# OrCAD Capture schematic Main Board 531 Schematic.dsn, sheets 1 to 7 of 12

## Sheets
1 01 INDEX: size A3; title: COMET10 EVAL board - Index; rev: 531; company: ST Microelectronics
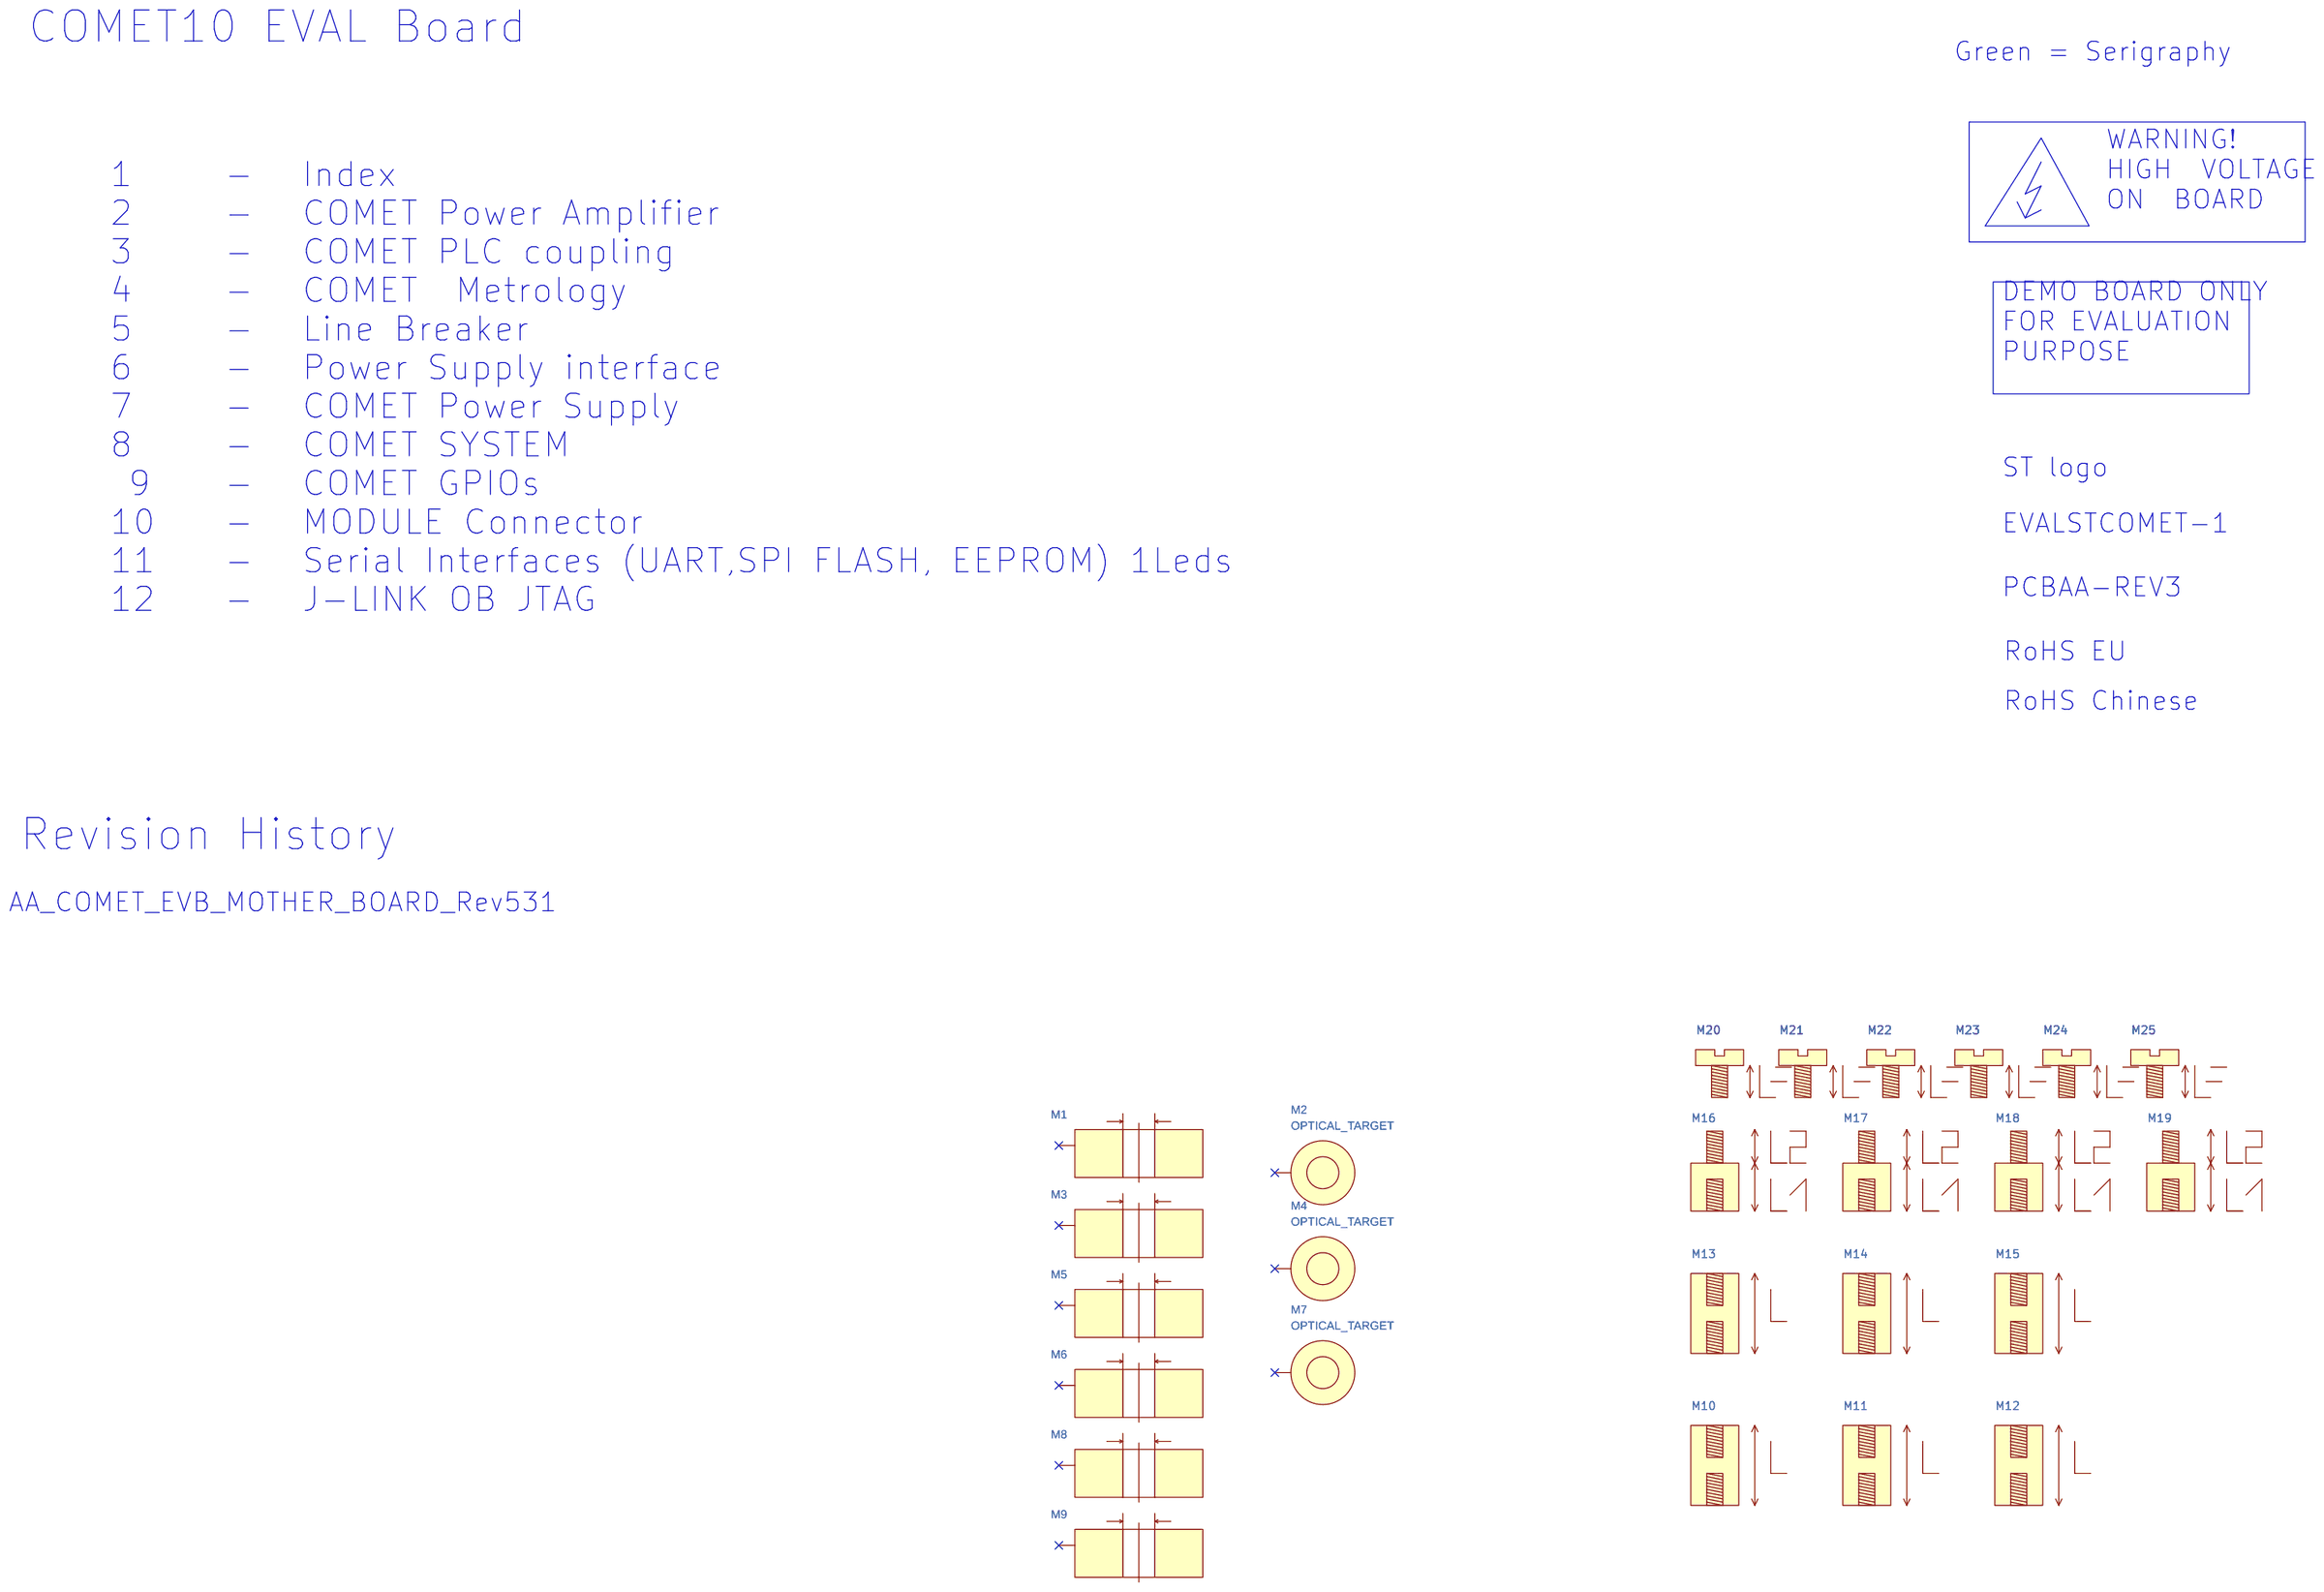
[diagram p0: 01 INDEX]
2 02 COMET POWER AMPLIFIER: size A3; title: COMET10 EVAL board - Differential power amplifier
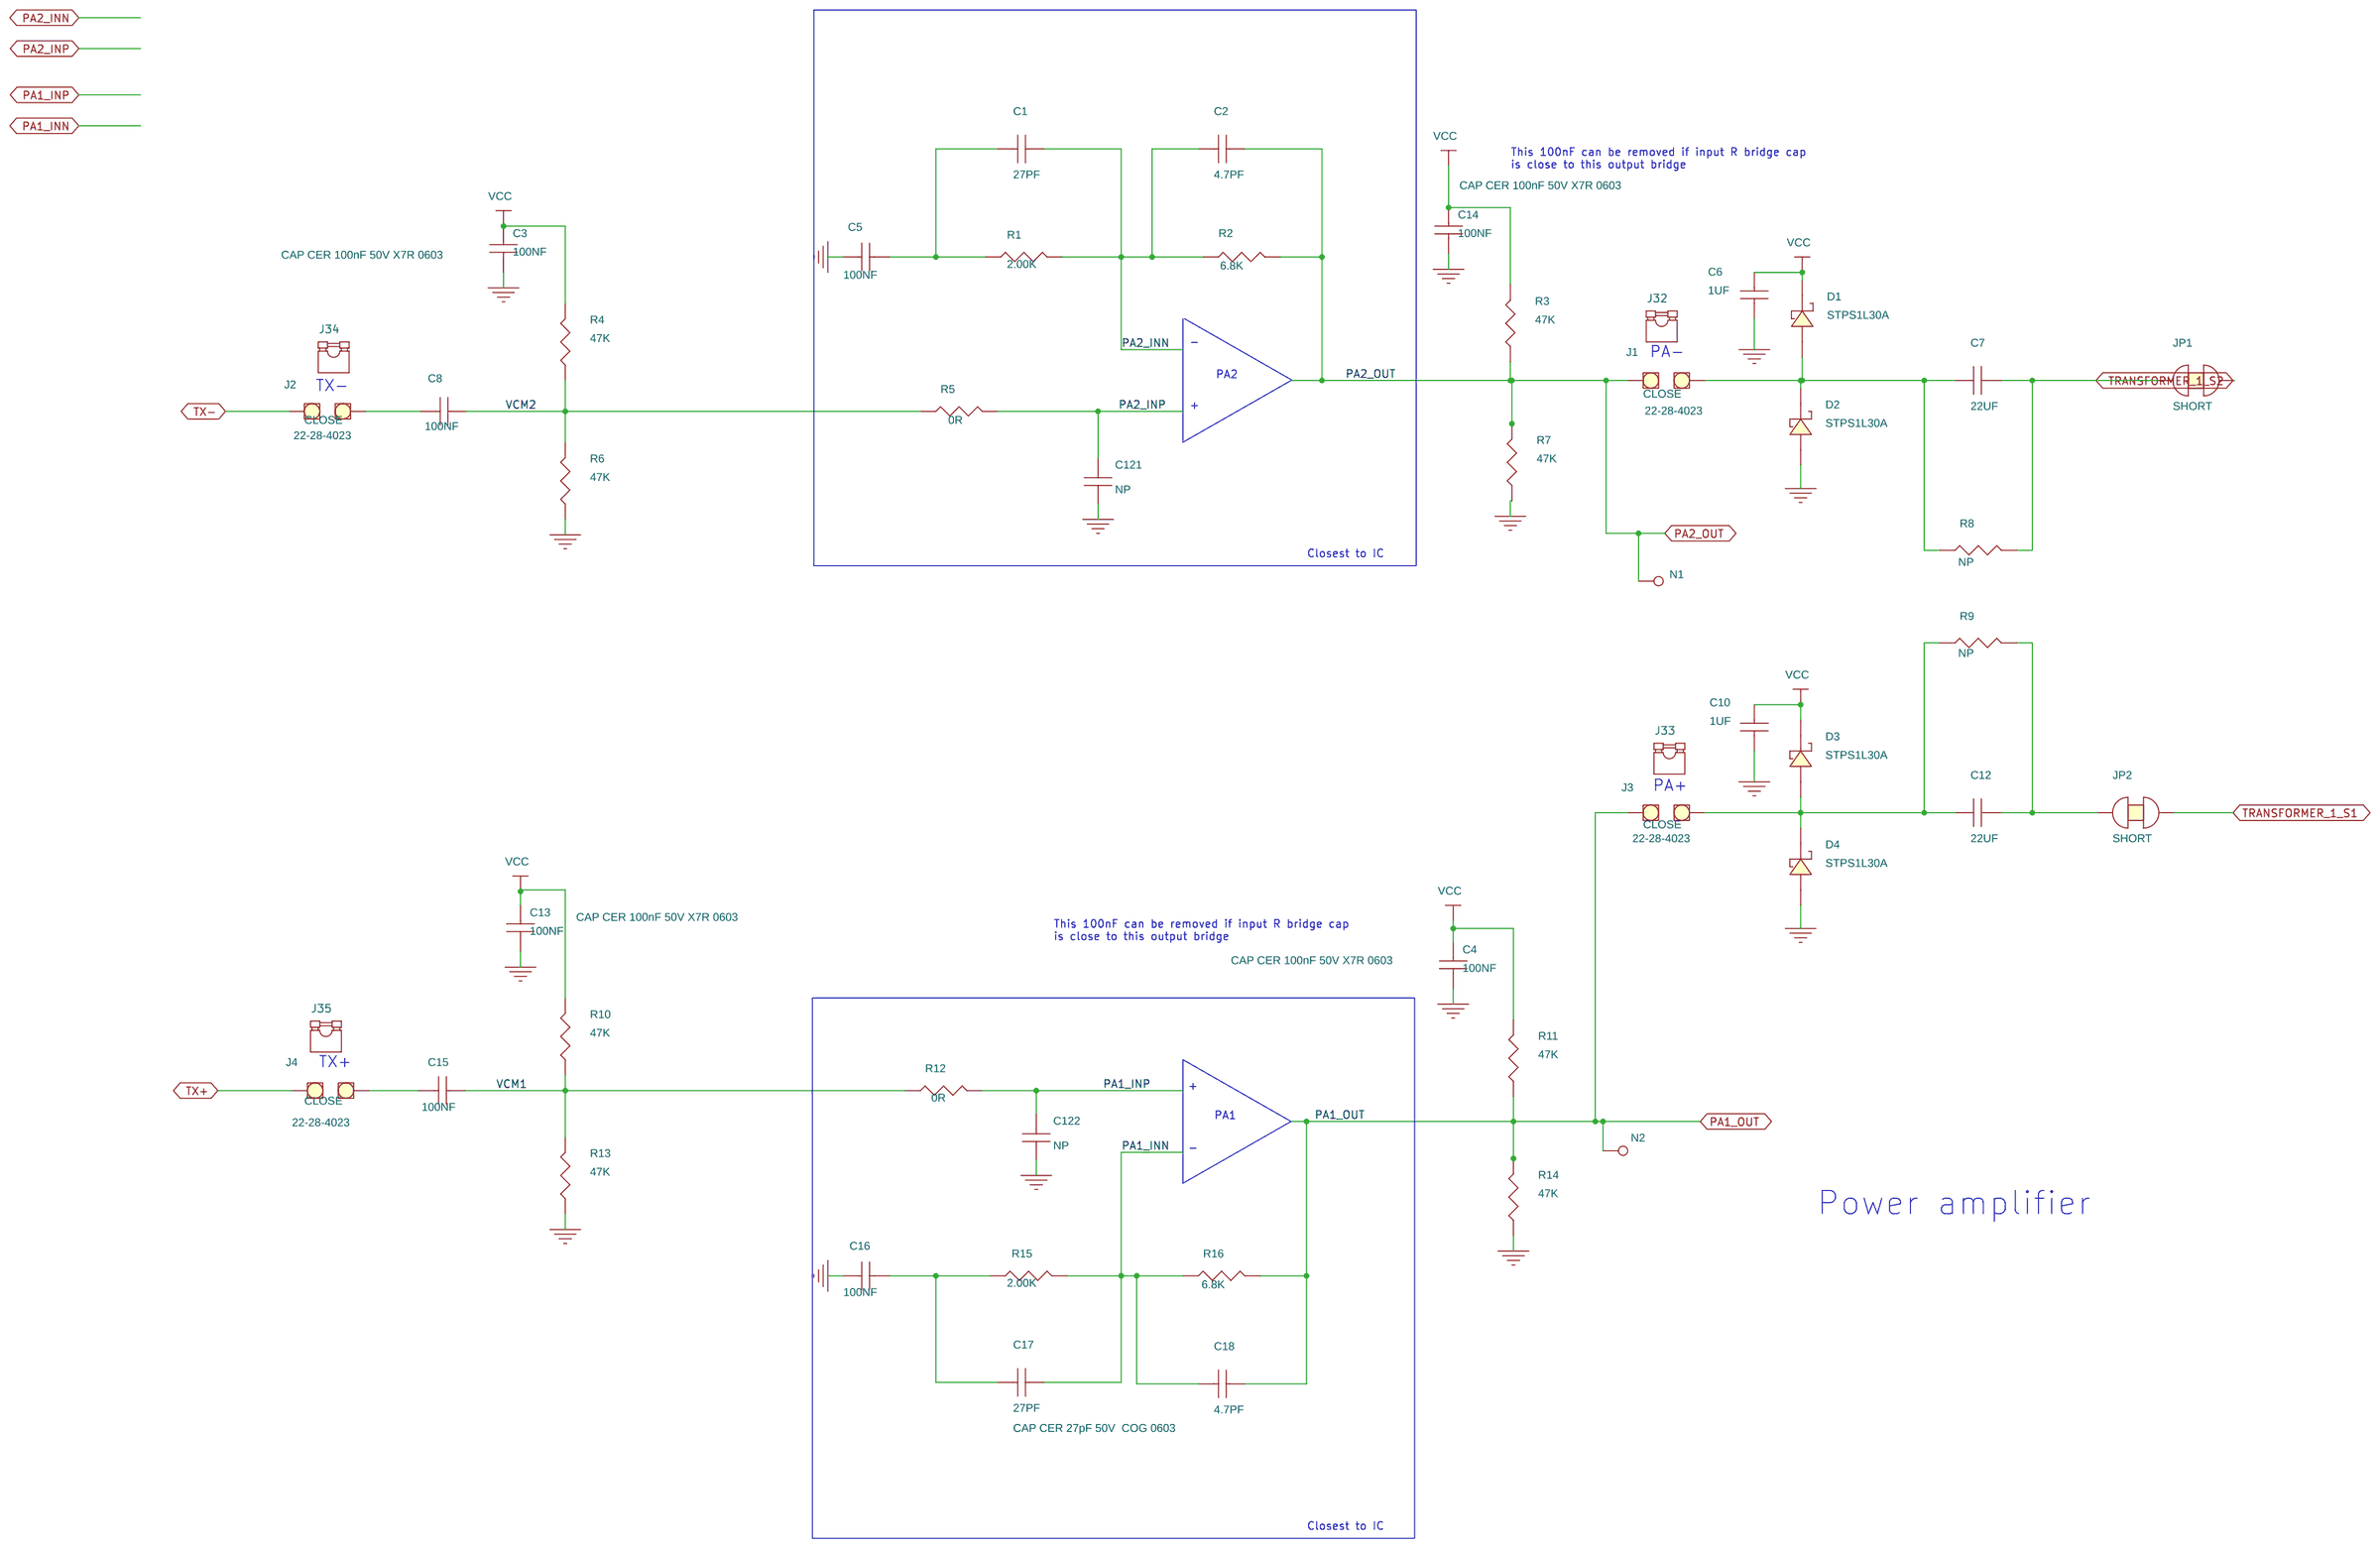
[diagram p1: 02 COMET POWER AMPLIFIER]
3 03 COMET PLC COUPLING: size A3; title: COMET10 EVAL board - PLC TX RX coupling, DAC, Zero Crossing
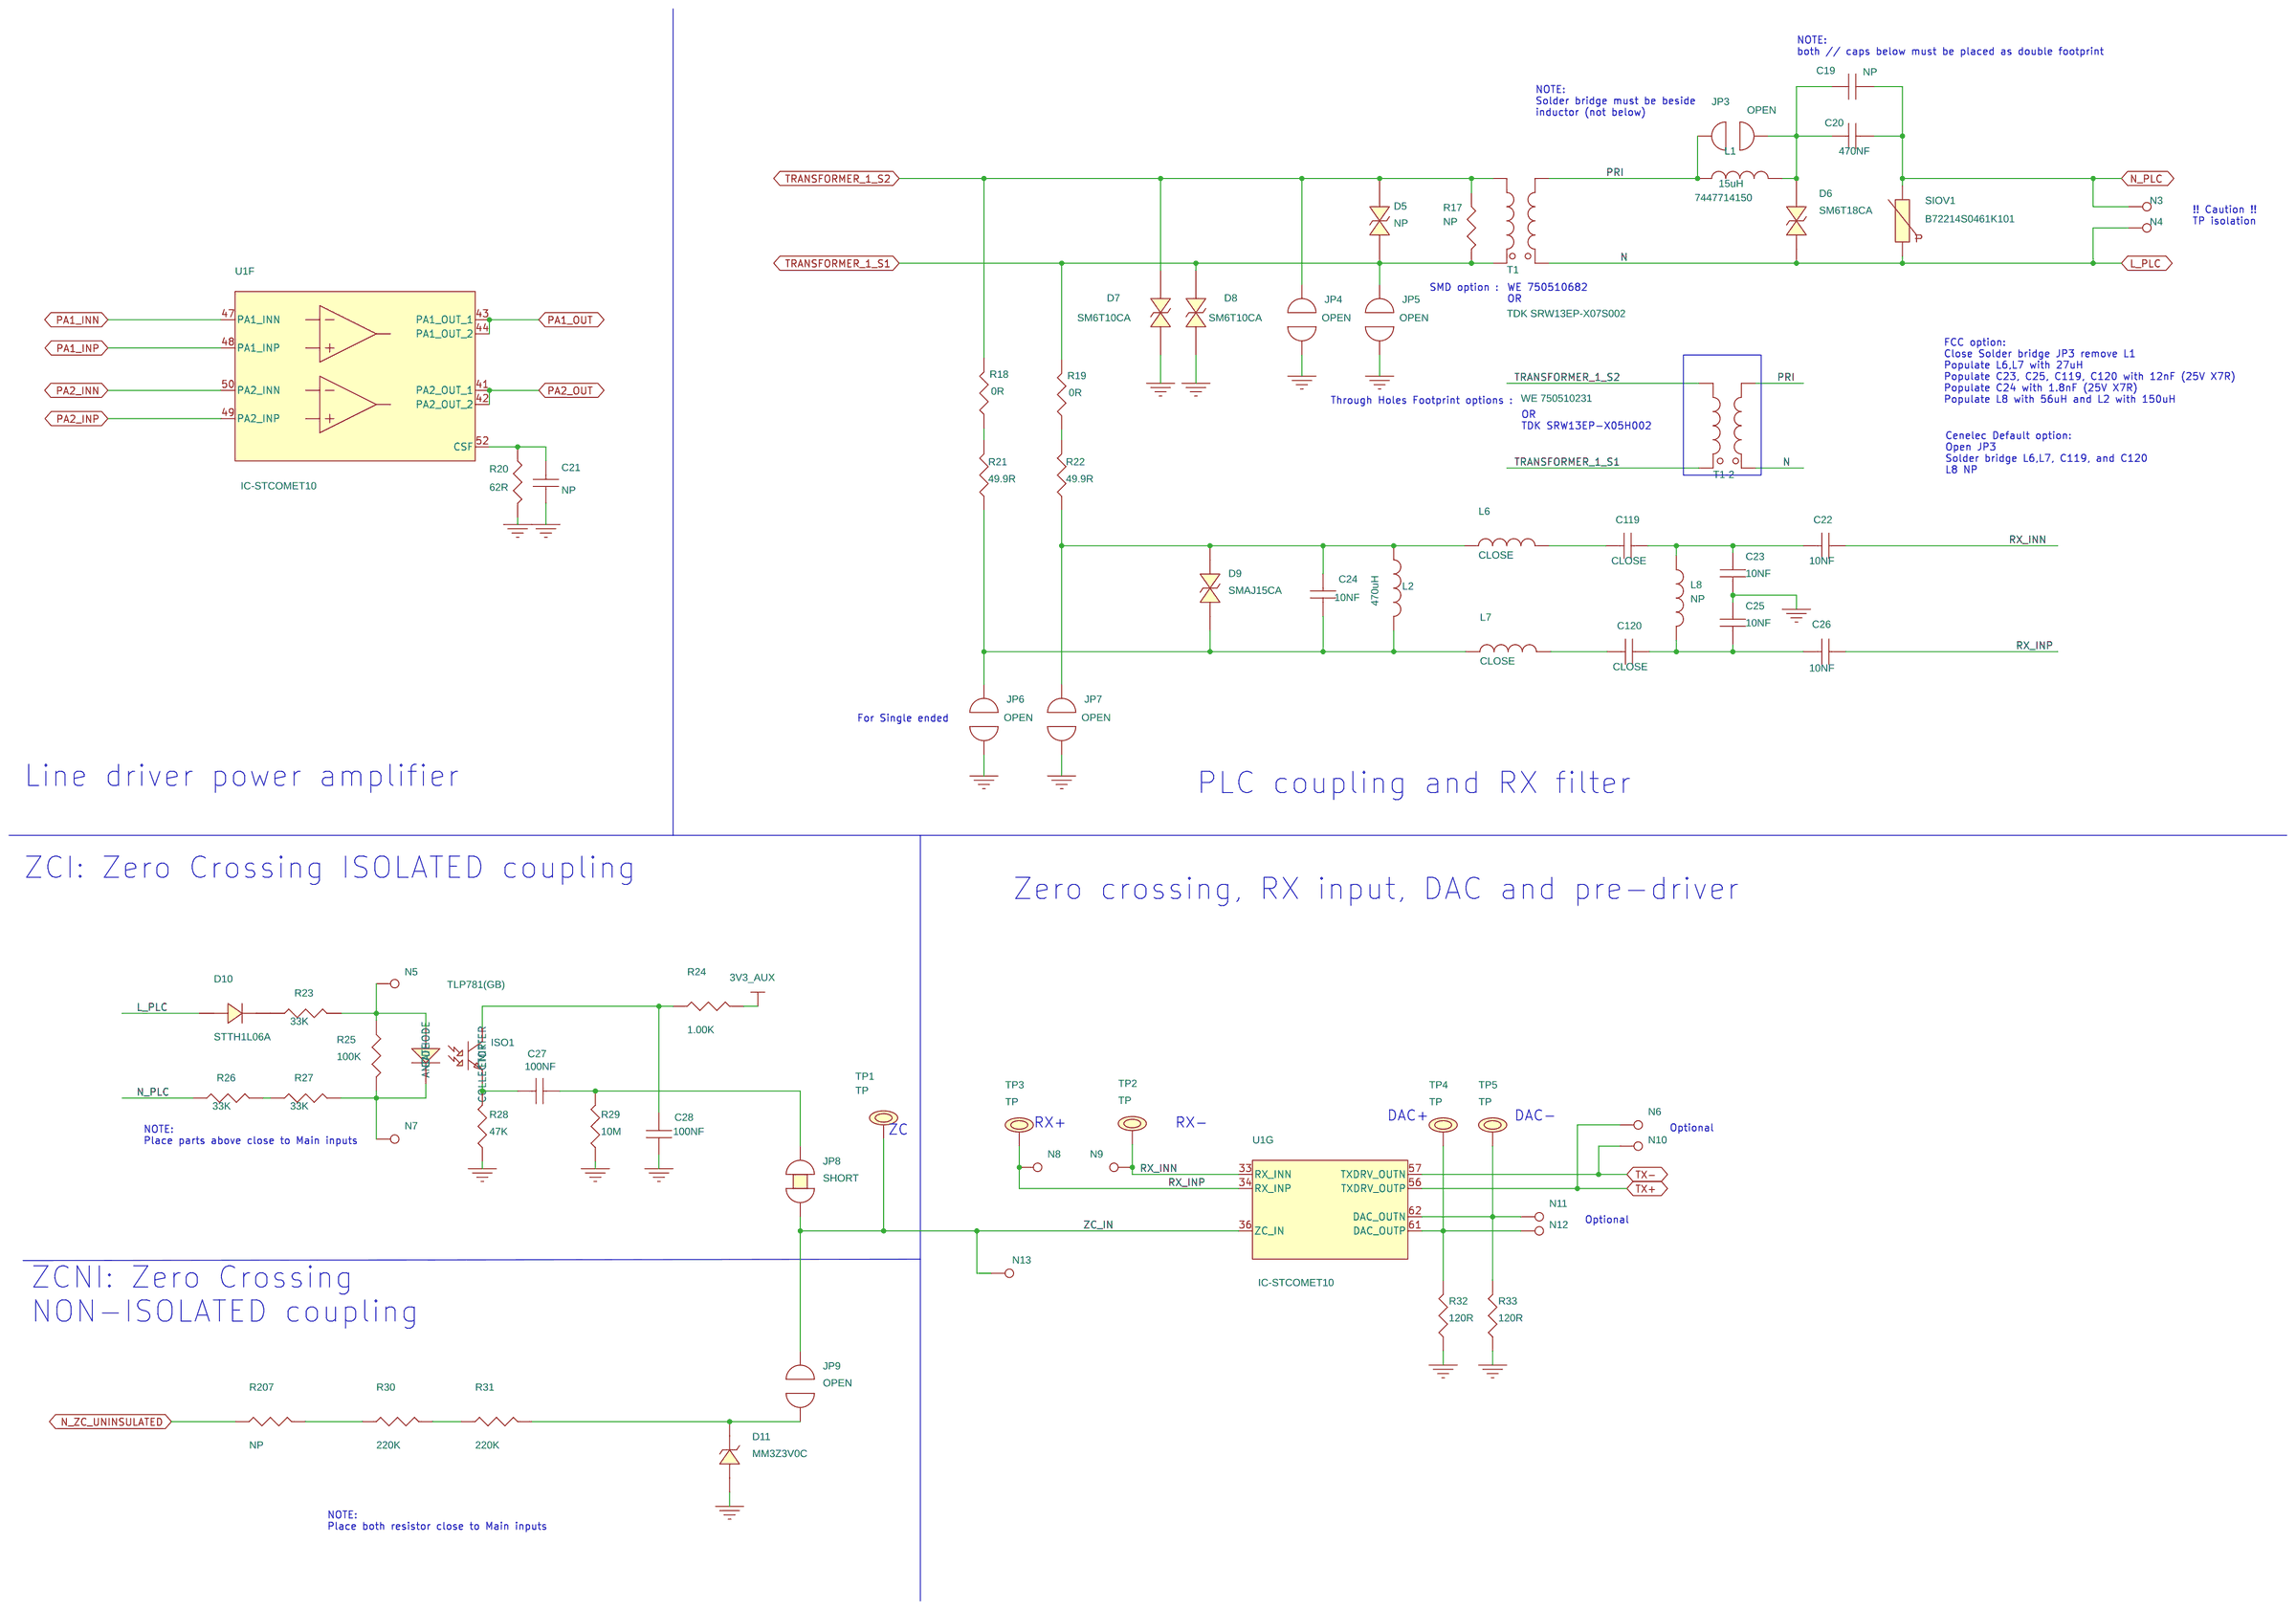
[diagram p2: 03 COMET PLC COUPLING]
4 04 COMET METROLOGY: size A3; title: COMET10 EVAL board - Metrology section
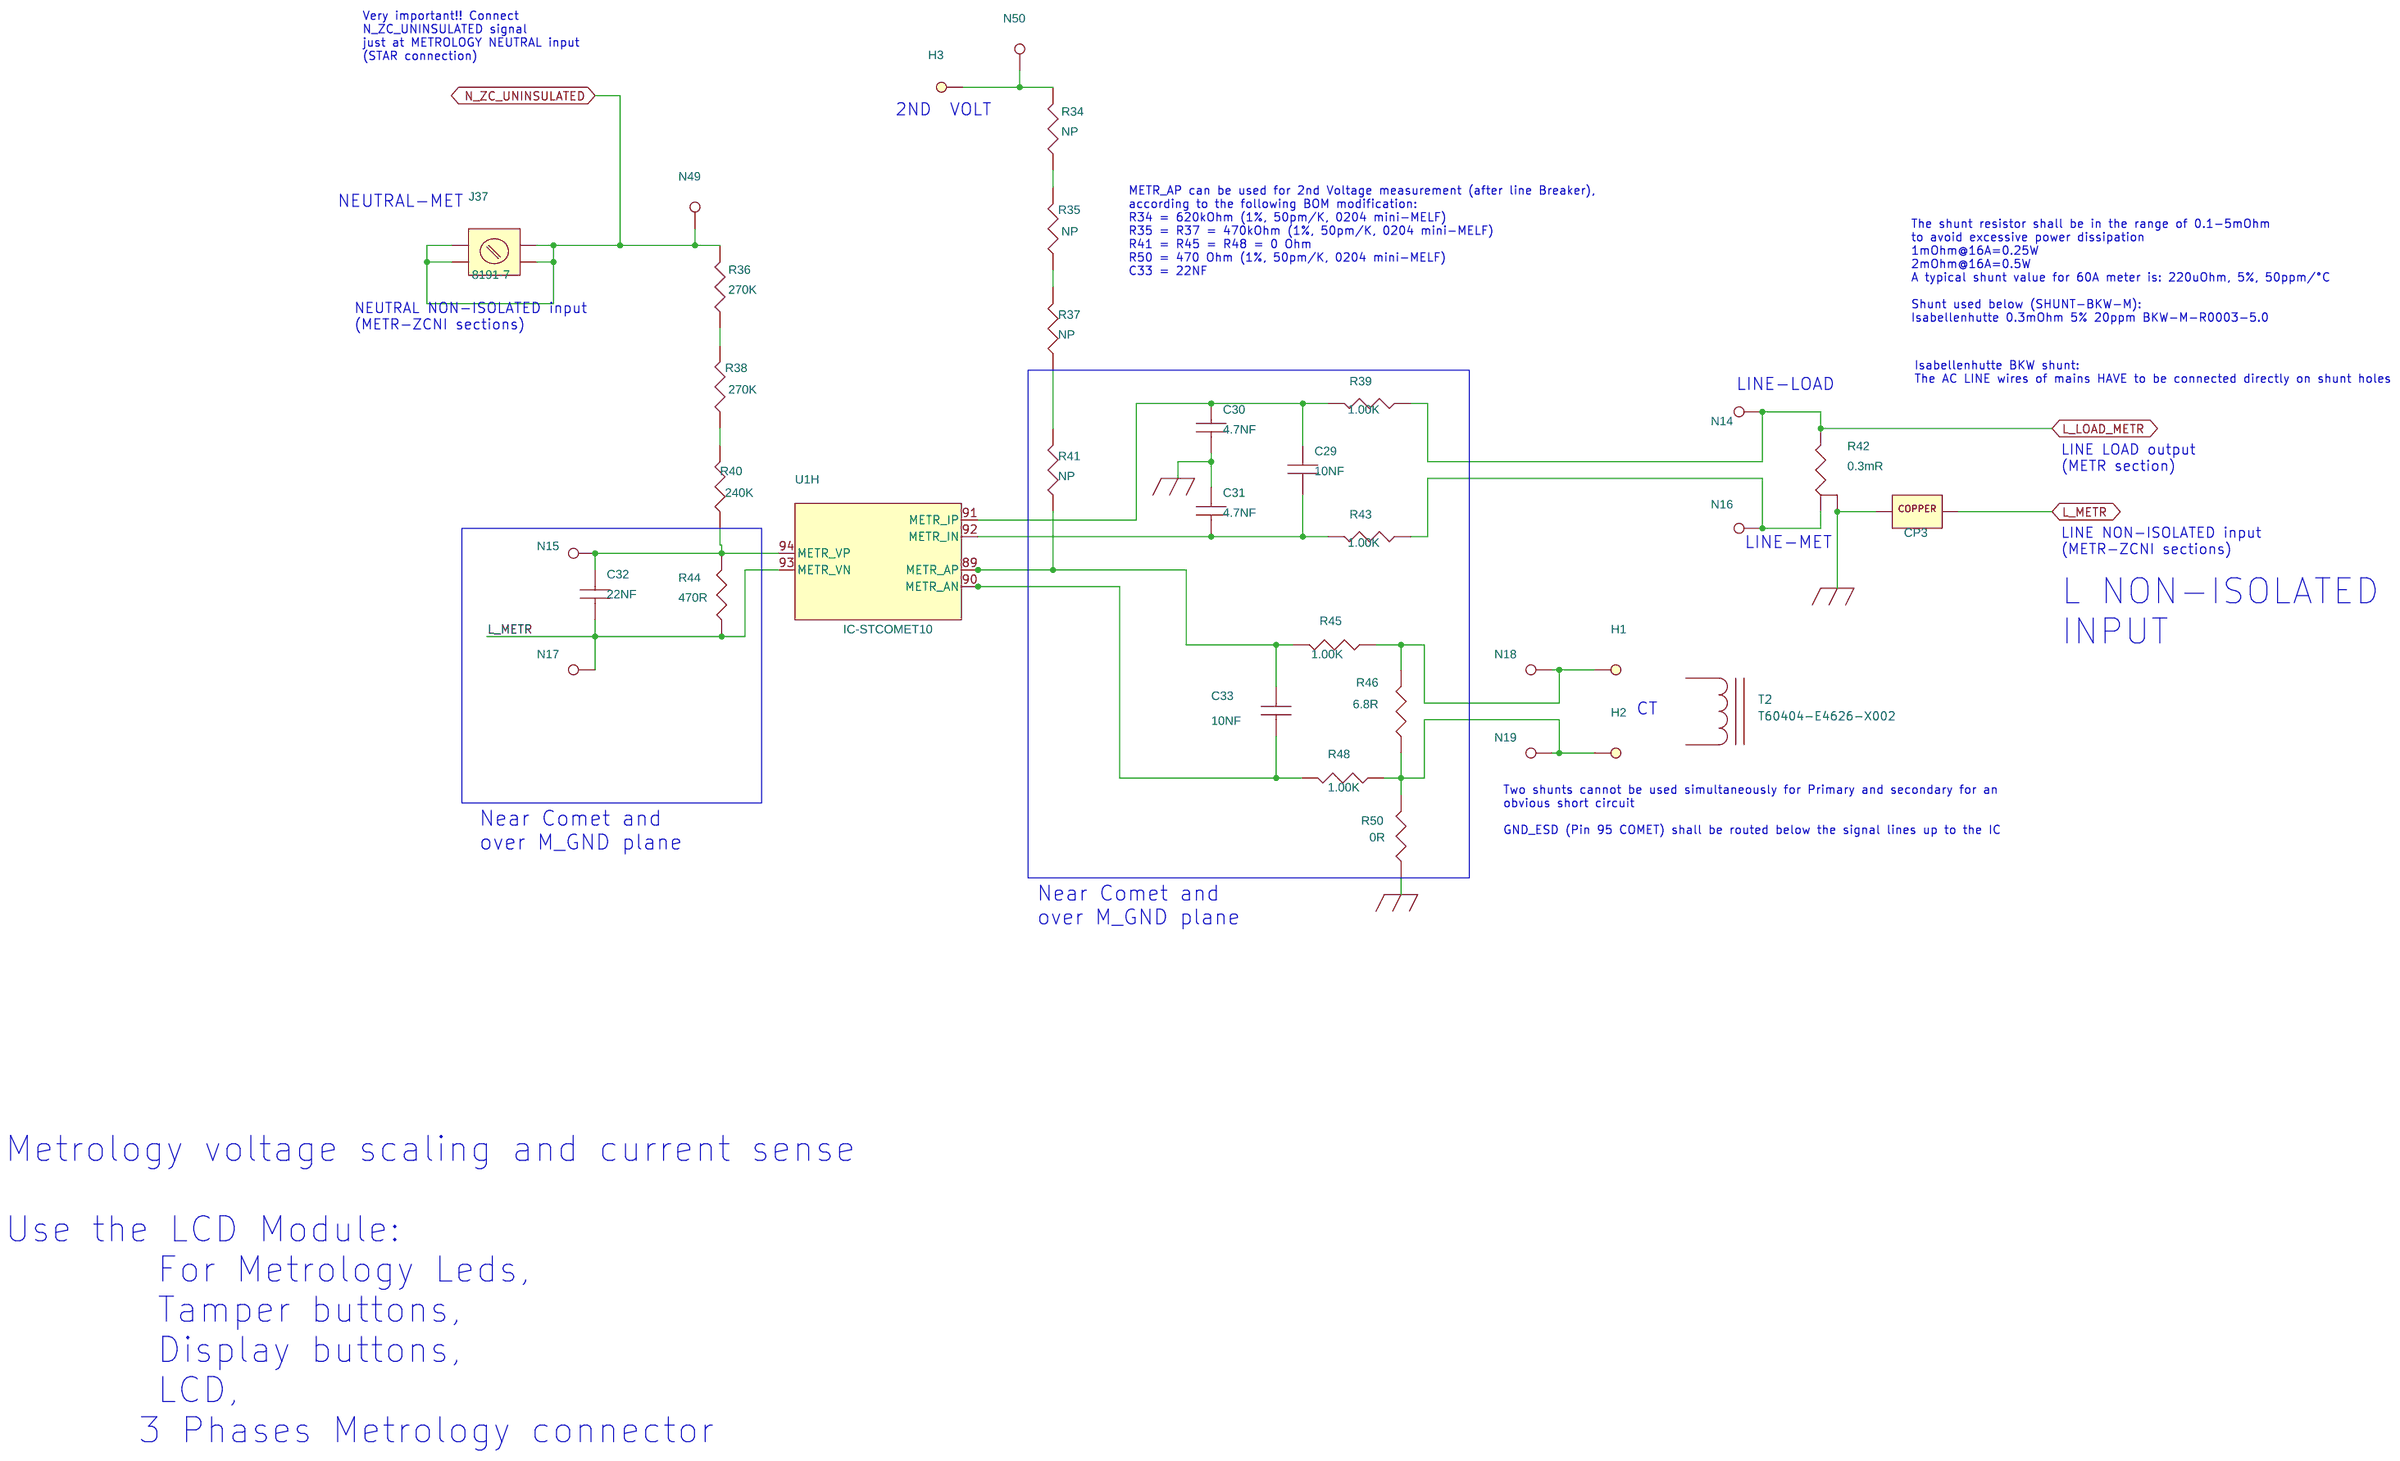
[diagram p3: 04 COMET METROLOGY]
5 05 LINE BREAKER: size A3; title: COMET10 EVAL board - Line Breaker section
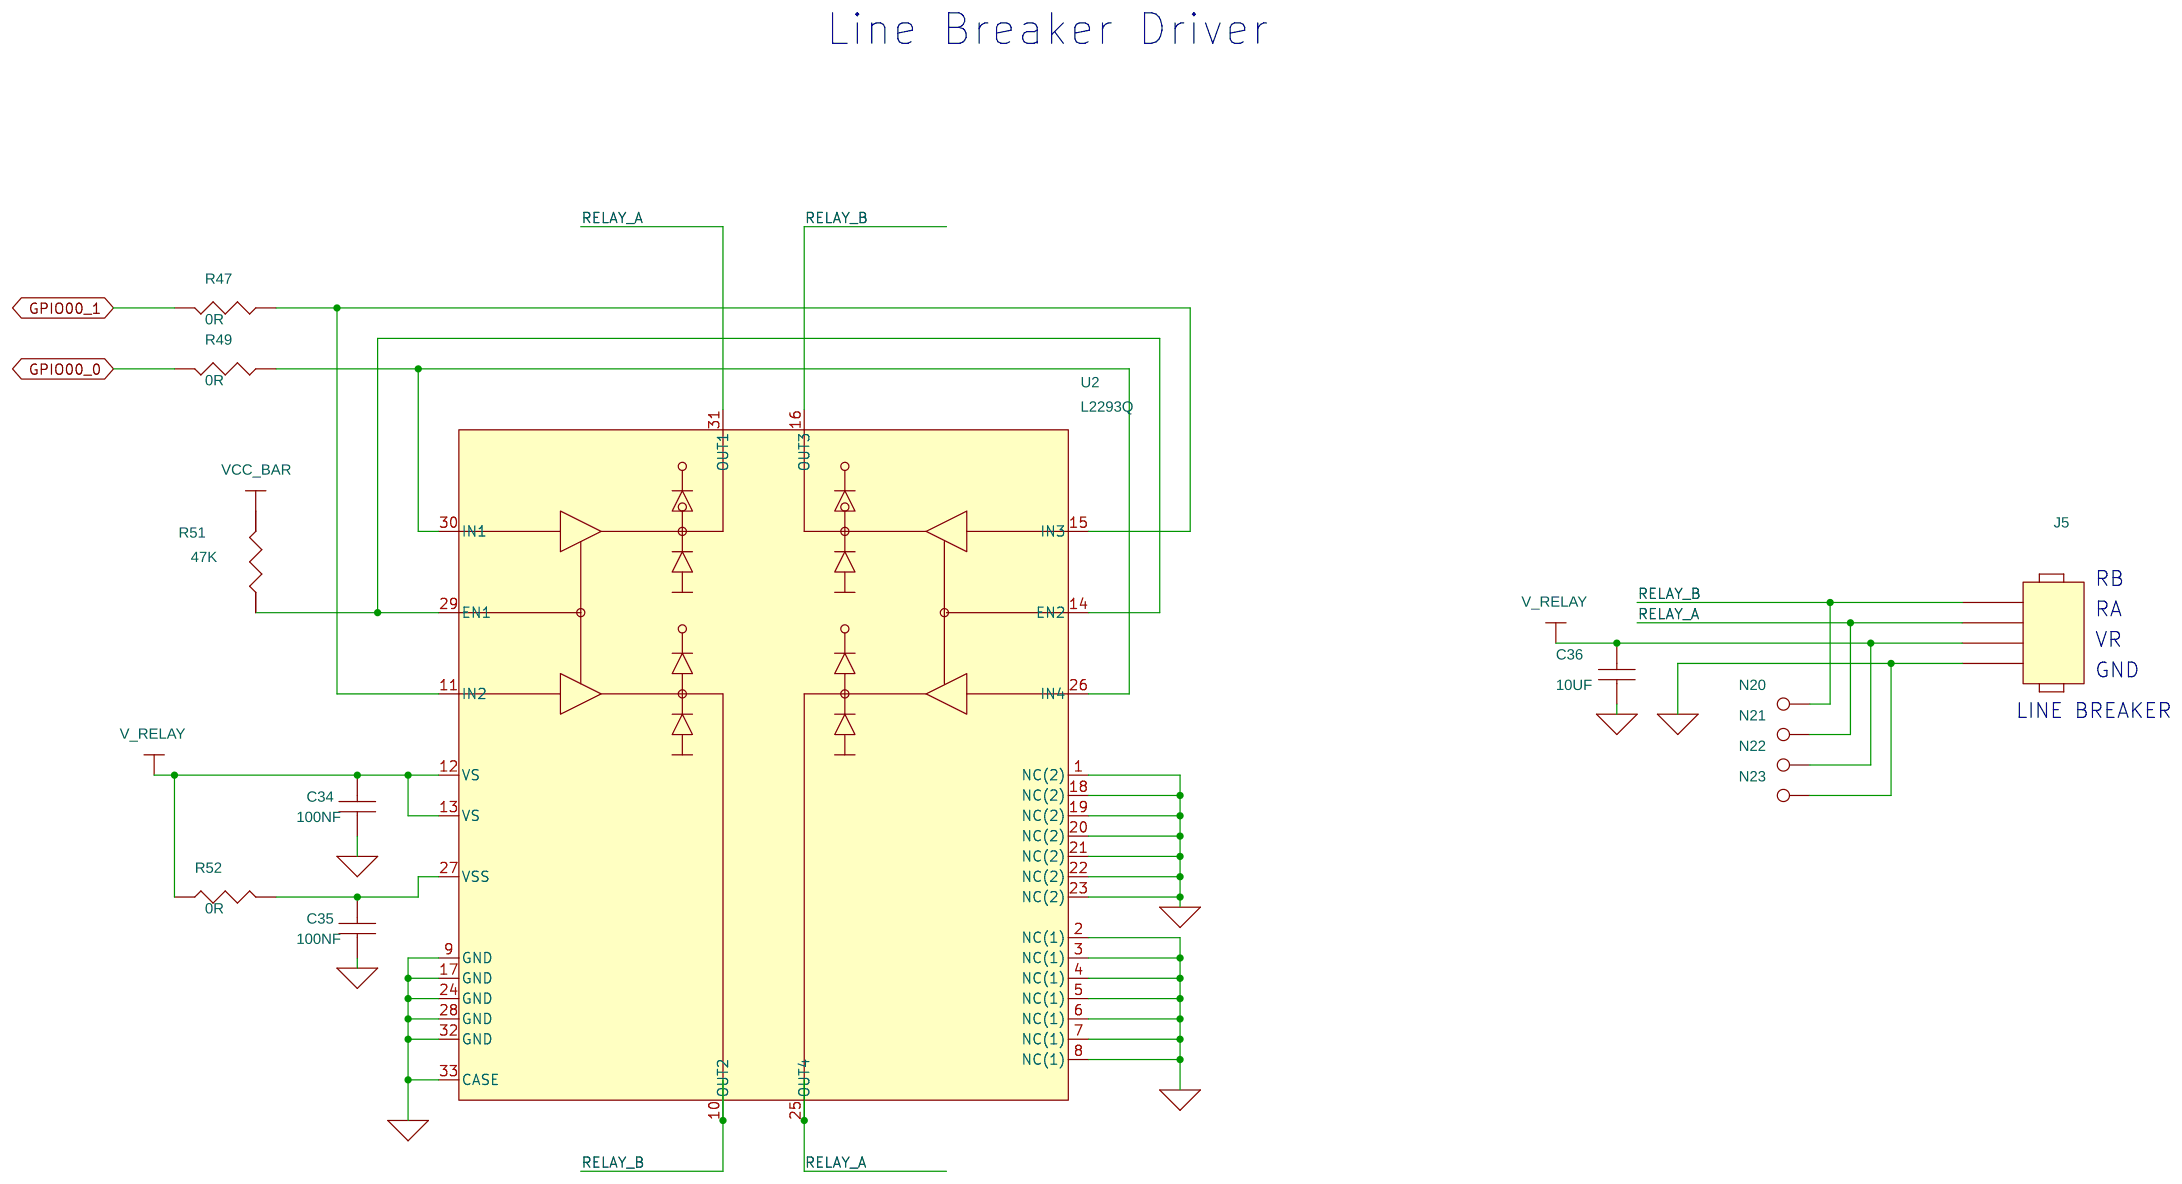
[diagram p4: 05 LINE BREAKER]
6 06 POWER SUPPLY: size A3; title: COMET10 EVAL board -  Power Supply interface section
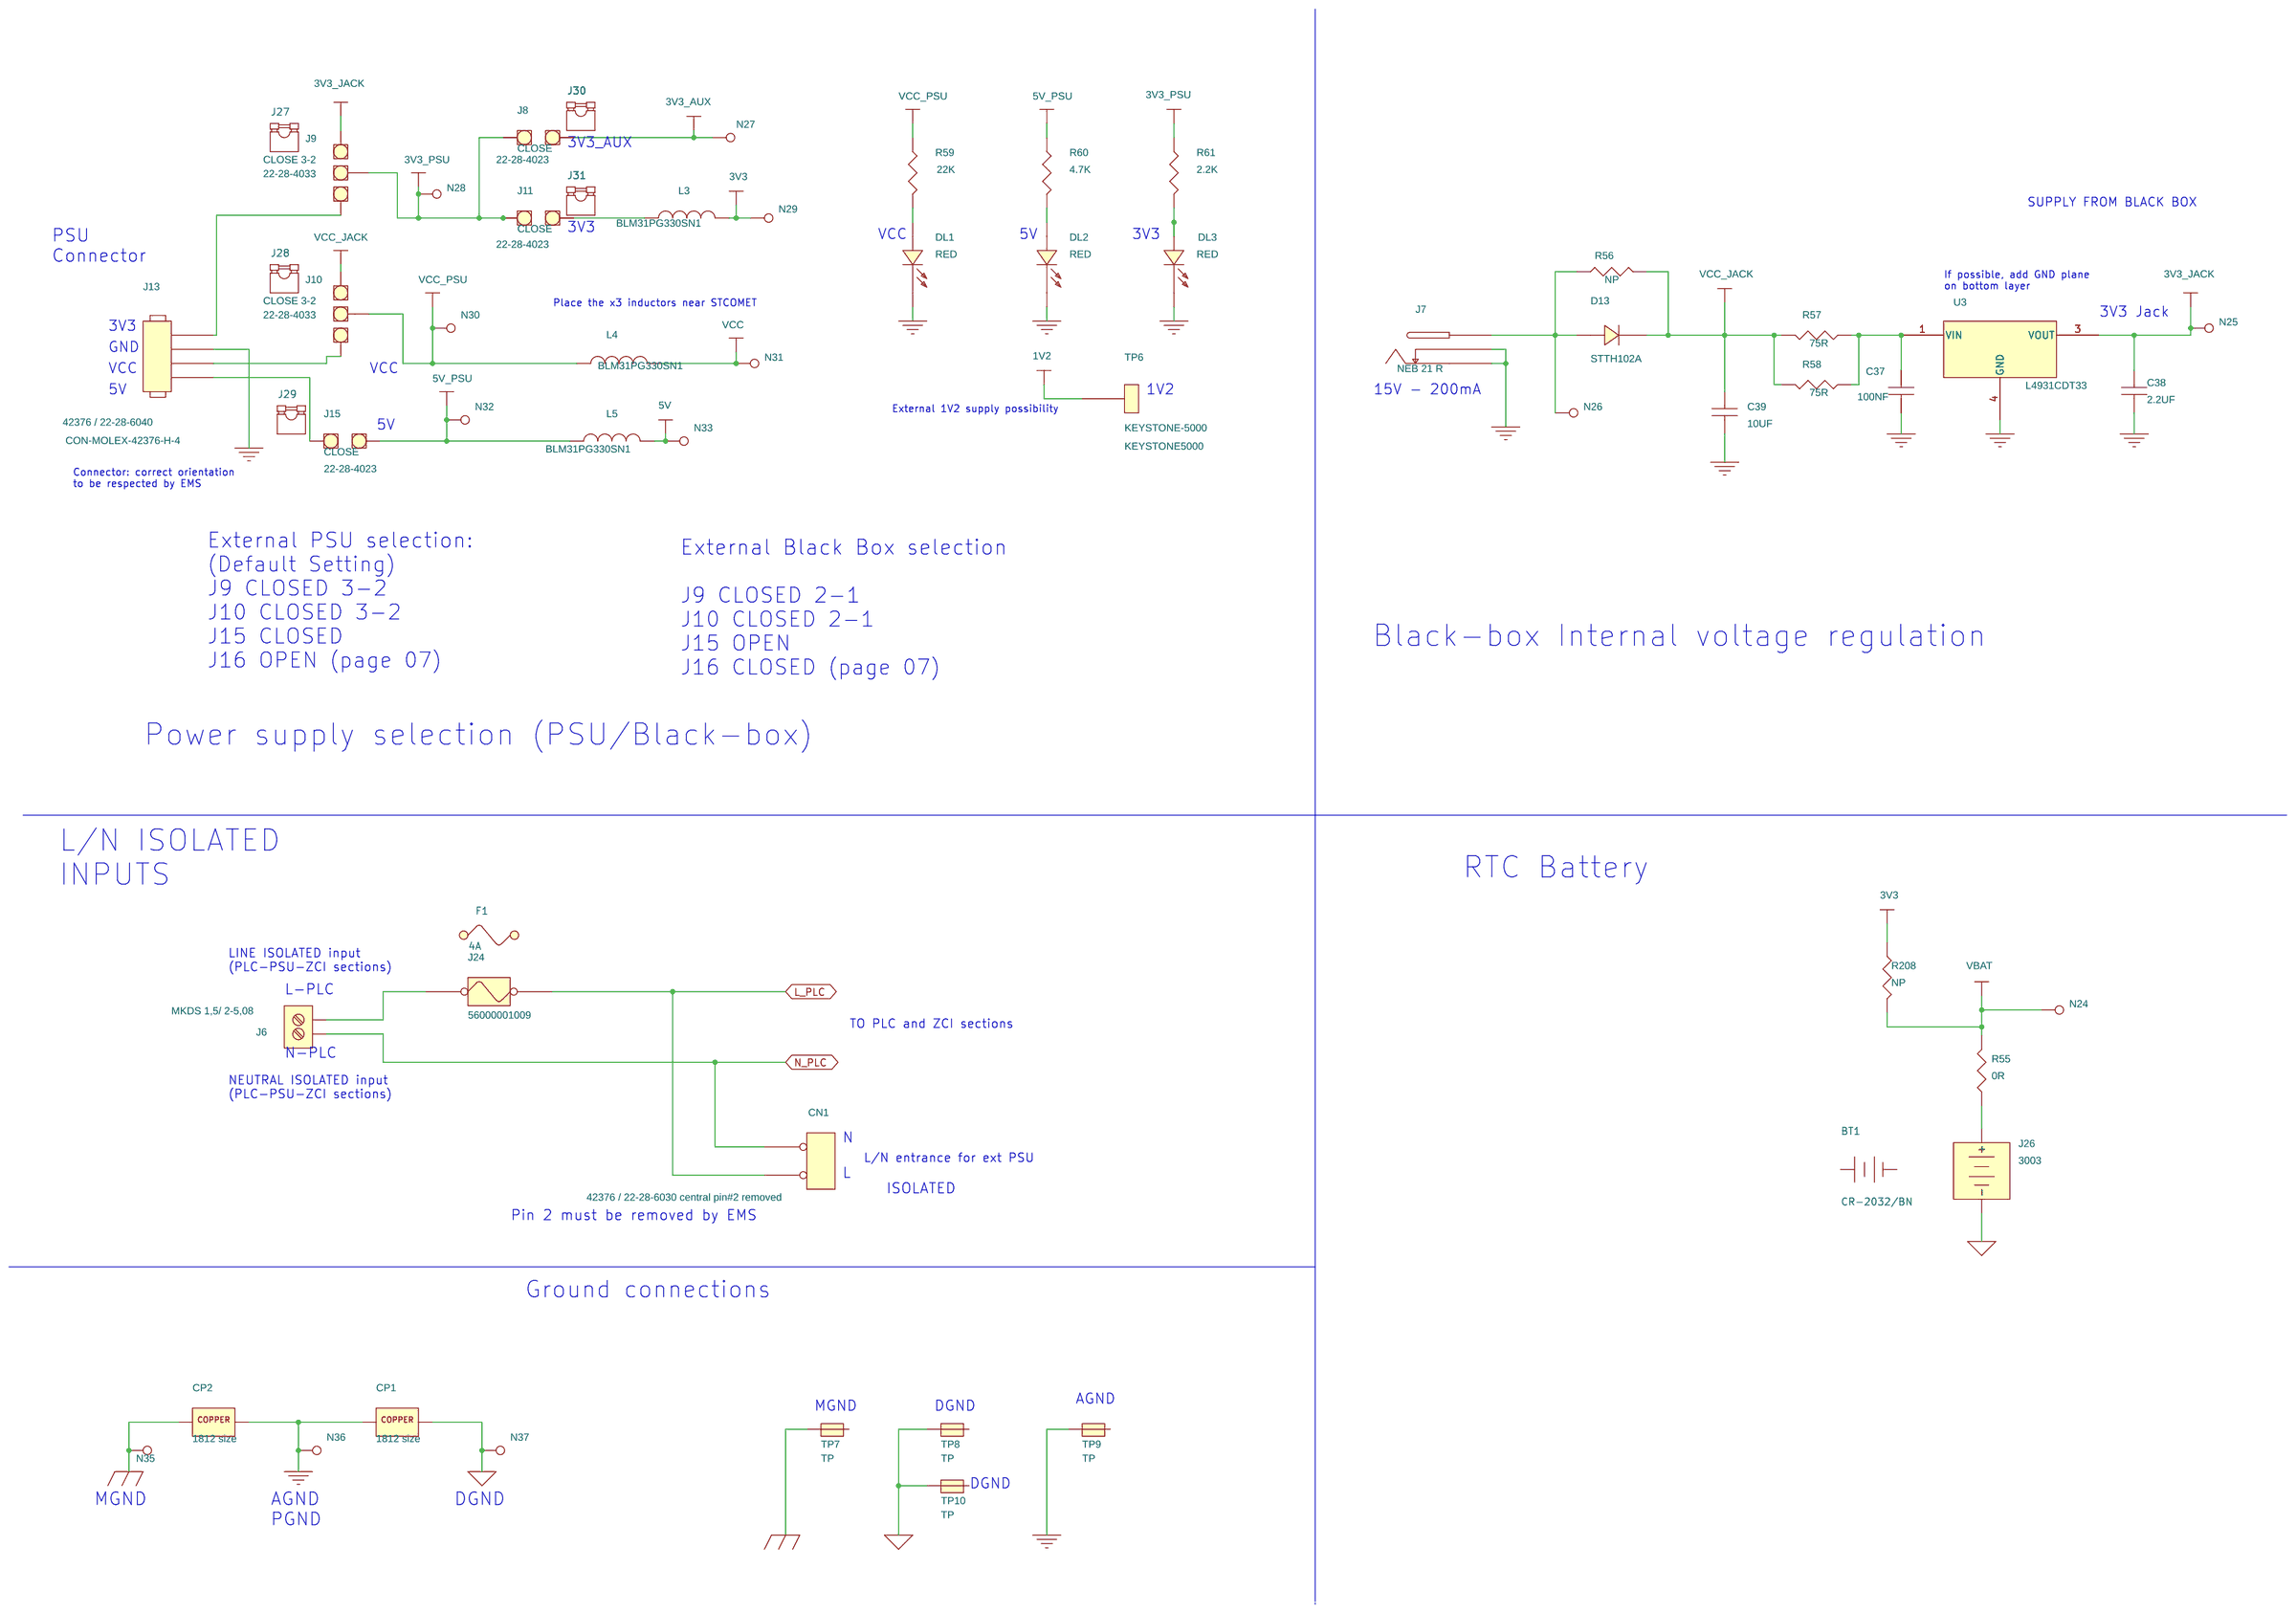
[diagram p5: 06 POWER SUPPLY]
7 07 COMET POWER SUPPLY: size A3; title: COMET10 debug board - COMET power supply section
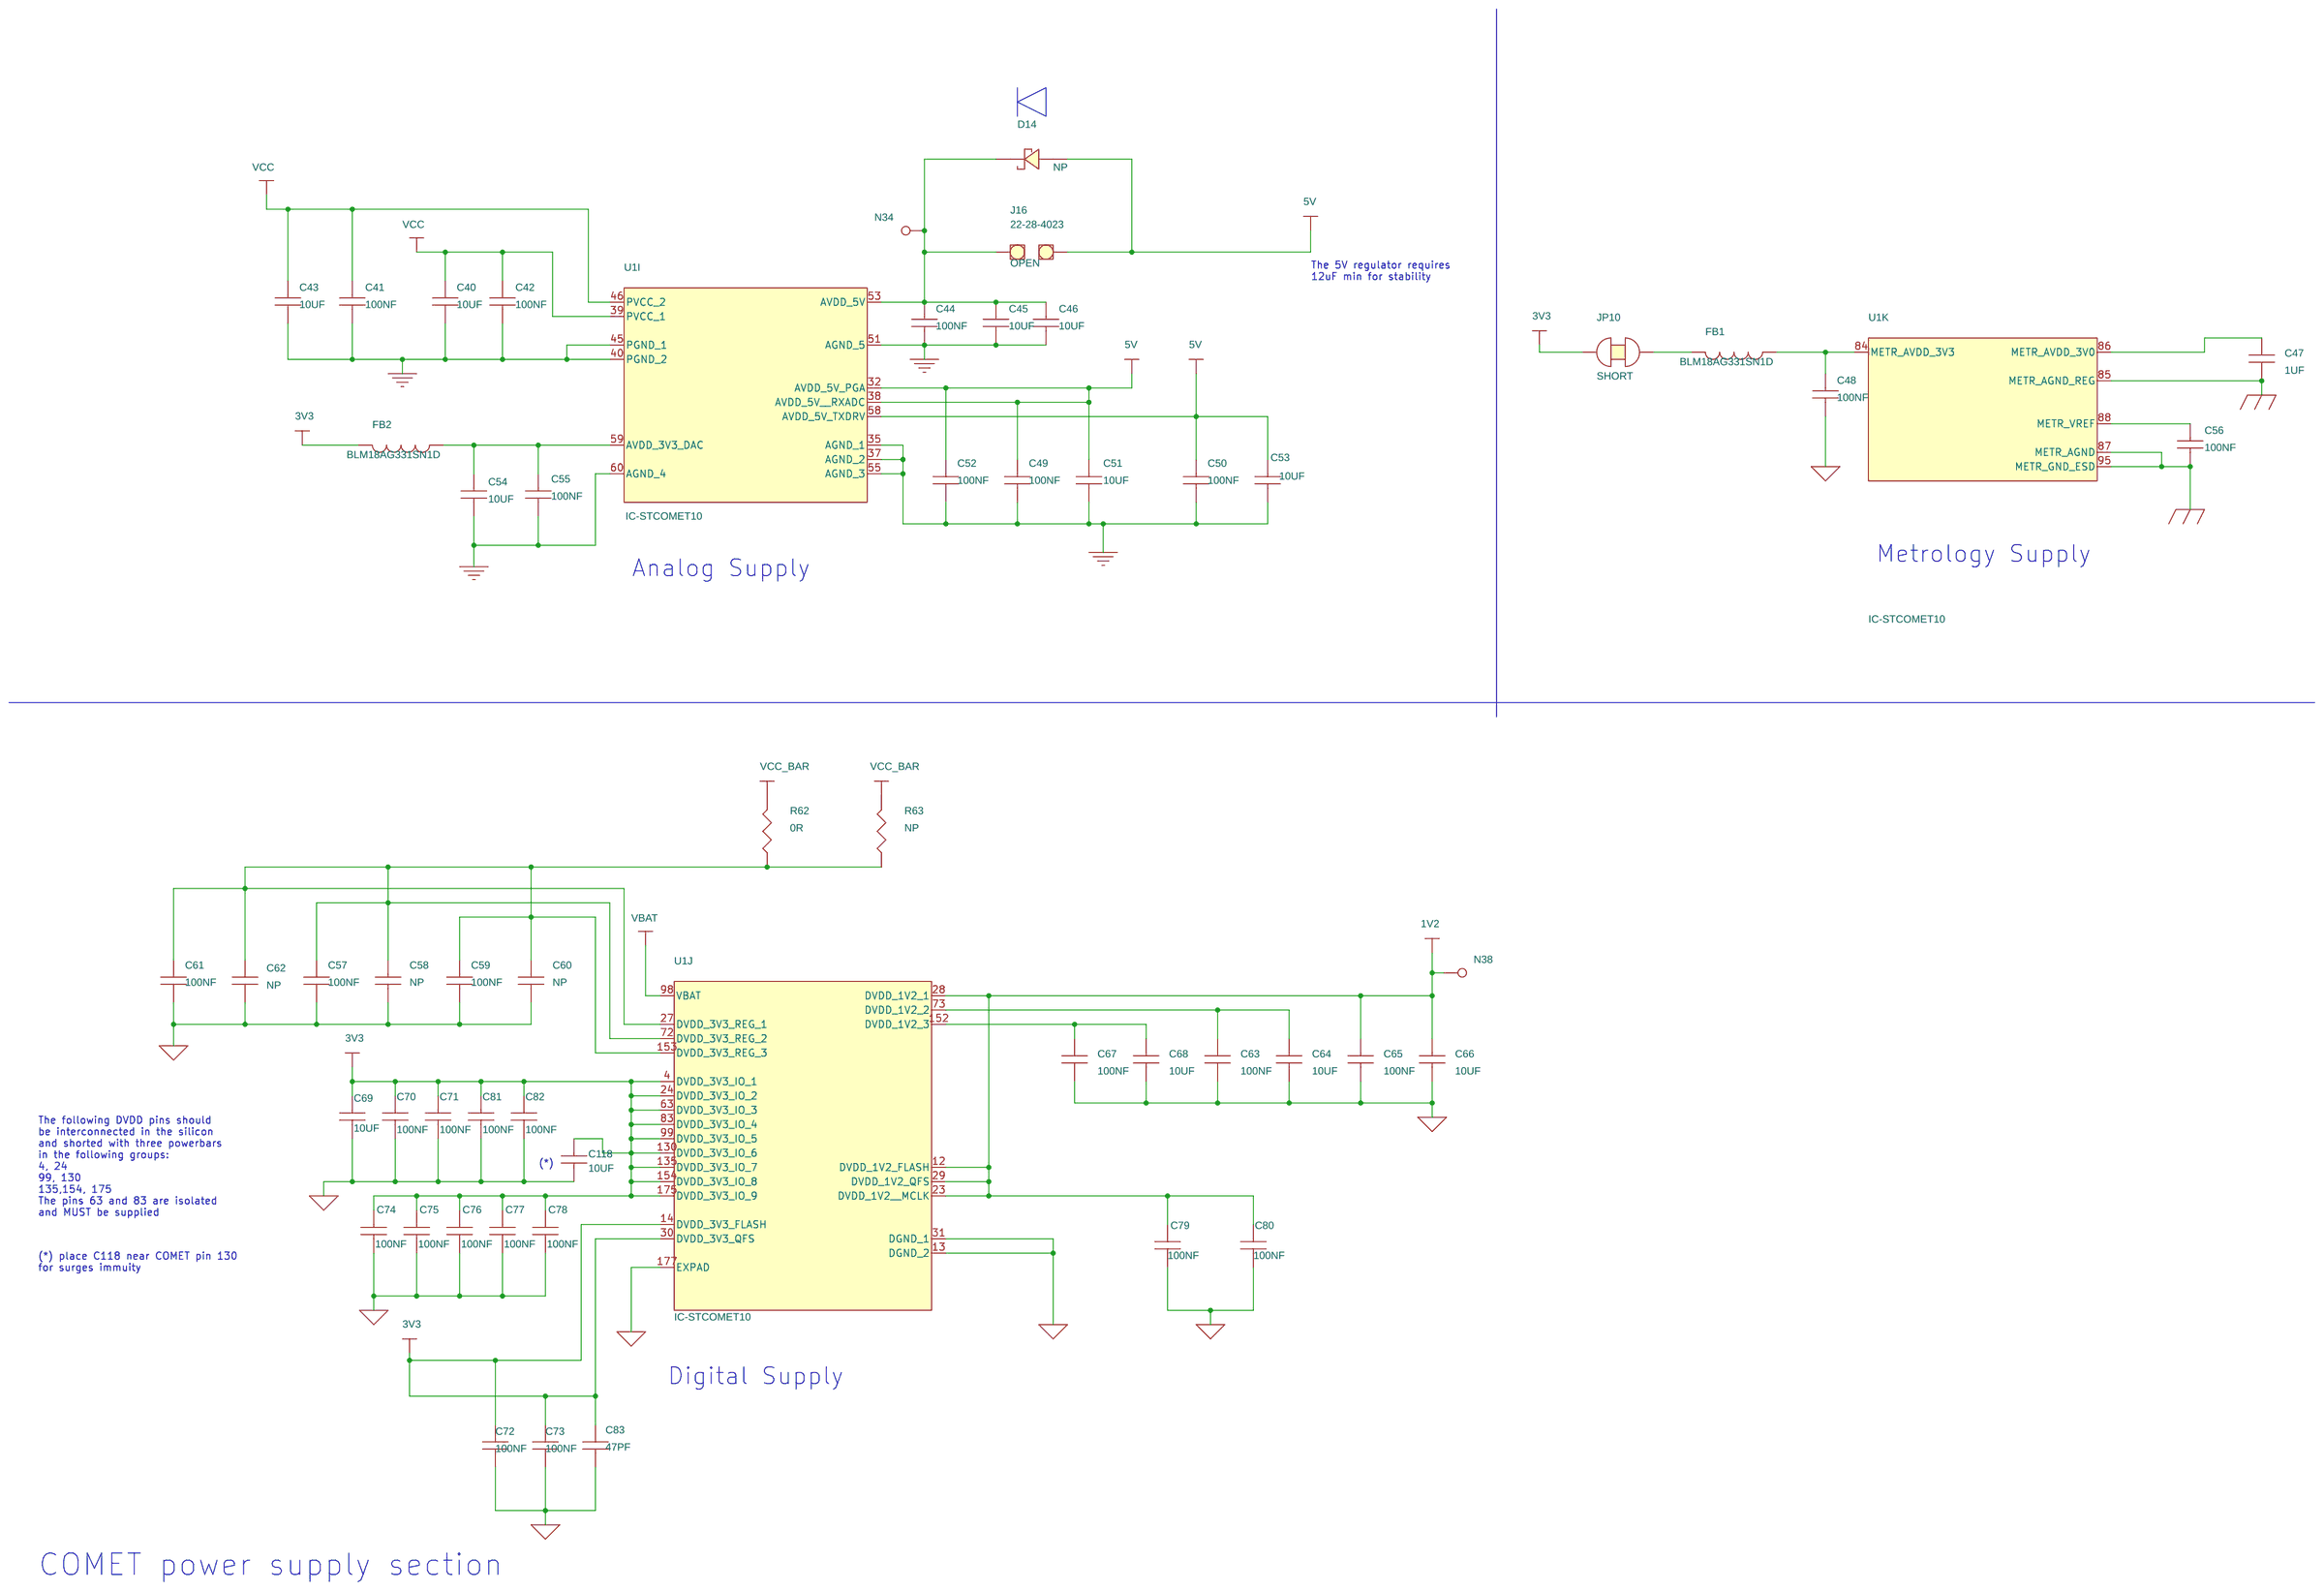
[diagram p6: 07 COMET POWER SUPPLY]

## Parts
sheet 01 INDEX
M1  -
M2  OPTICAL_TARGET
M3  -
M4  OPTICAL_TARGET
M5  -
M6  -
M7  OPTICAL_TARGET
M8  -
M9  -
M10  NYLON; M3; L=12mm
M11  NYLON; M3; L=12mm
M12  NYLON; M3; L=12mm
M13  NYLON; M3; L=12mm
M14  NYLON; M3; L=12mm
M15  NYLON; M3; L=12mm
M16  BRASS; M3; L1=5mm; L2=5mm
M17  BRASS; M3; L1=5mm; L2=5mm
M18  BRASS; M3; L1=5mm; L2=5mm
M19  BRASS; M3; L1=5mm; L2=5mm
M20  NYLON; M3; L=4mm
M21  NYLON; M3; L=4mm
M22  NYLON; M3; L=4mm
M23  NYLON; M3; L=4mm
M24  NYLON; M3; L=4mm
M25  NYLON; M3; L=4mm
sheet 02 COMET POWER AMPLIFIER
C1  27PF  [0603]
C2  4.7PF  [0603]
C3  100NF  [0603]
C4  100NF  [0603]
C5  100NF  [0603]
C6  1UF  [0805]
C7  22UF  [1206]
C8  100NF  [0603]
C10  1UF  [0805]
C12  22UF  [1206]
C13  100NF  [0603]
C14  100NF  [0603]
C15  100NF  [0603]
C16  100NF  [0603]
C17  27PF  [0603]
C18  4.7PF  [0603]
C121  NP  [0402]
C122  NP  [0402]
D1  STPS1L30A  [DO214AC]
D2  STPS1L30A  [DO214AC]
D3  STPS1L30A  [DO214AC]
D4  STPS1L30A  [DO214AC]
J1  CLOSE  [22-28-4023]
J2  CLOSE  [22-28-4023]
J3  CLOSE  [22-28-4023]
J4  CLOSE  [22-28-4023]
J32  JUMPER 2.54  [JUMP254P-M-2]
J33  JUMPER 2.54  [JUMP254P-M-2]
J34  JUMPER 2.54  [JUMP254P-M-2]
J35  JUMPER 2.54  [JUMP254P-M-2]
JP1  SHORT  [JP2SO]
JP2  SHORT  [JP2SO]
N1  TP  [TPSMD-40RD]
N2  TP  [TPSMD-40RD]
R1  2.00K  [0603]
R2  6.8K  [0603]
R3  47K  [0603]
R4  47K  [0603]
R5  0R  [0603]
R6  47K  [0603]
R7  47K  [0603]
R8  NP  [0805]
R9  NP  [0805]
R10  47K  [0603]
R11  47K  [0603]
R12  0R  [0603]
R13  47K  [0603]
R14  47K  [0603]
R15  2.00K  [0603]
R16  6.8K  [0603]
sheet 03 COMET PLC COUPLING
C19  NP
C20  470NF  [CAPP-265X100x165-P225]
C21  NP  [0402]
C22  10NF  [0603]
C23  10NF  [0603]
C24  10NF  [0603]
C25  10NF  [0603]
C26  10NF  [0603]
C27  100NF  [0603]
C28  100NF  [0603]
C119  CLOSE  [0303]
C120  CLOSE  [0303]
D5  NP
D6  SM6T18CA  [DO214AA]
D7  SM6T10CA  [DO214AA]
D8  SM6T10CA  [DO214AA]
D9  SMAJ15CA  [DO214AB]
D10  STTH1L06A  [SMA]
D11  MM3Z3V0C  [SOD323F]
ISO1  TLP781(GB)  [DIP4]
JP3  OPEN  [JP2SO]
JP4  OPEN  [JP2SO]
JP5  OPEN  [JP2SO]
JP6  OPEN  [JP2SO]
JP7  OPEN  [JP2SO]
JP8  SHORT  [JP2SO]
JP9  OPEN  [JP2SO]
L1  15uH  [Coil]
L2  470uH  [1812]
L6  CLOSE  [4828]
L7  CLOSE  [4828]
L8  NP  [4818]
N3  TP  [TPSMD-40RD]
N4  TP  [TPSMD-40RD]
N5  TP  [TPSMD-40RD]
N6  TP  [TPSMD-40RD]
N7  TP  [TPSMD-40RD]
N8  TP  [TPSMD-40RD]
N9  TP  [TPSMD-40RD]
N10  TP  [TPSMD-40RD]
N11  TP  [TPSMD-40RD]
N12  TP  [TPSMD-40RD]
N13  TP  [TPSMD-40RD]
R17  NP  [1206]
R18  0R  [0603]
R19  0R  [0603]
R20  62R  [0603]
R21  49.9R  [0603]
R22  49.9R  [0603]
R23  33K  [1206]
R24  1.00K  [0603]
R25  100K  [0805]
R26  33K  [1206]
R27  33K  [1206]
R28  47K  [0603]
R29  10M  [0603]
R30  220K  [1206]
R31  220K  [1206]
R32  120R  [0603]
R33  120R  [0603]
R207  NP  [1206]
SIOV1  B72214S0461K101
T1  TDK SRW13EP-X07S002  [TRAFO-TDK-SRW13EP-X07]
T1-2  WE 750510231  [TRAFO-WE-750-510-231]
TP1  TP  [TPTH-ANELLO-1MM]
TP2  TP  [TPTH-ANELLO-1MM]
TP3  TP  [TPTH-ANELLO-1MM]
TP4  TP  [TPTH-ANELLO-1MM]
TP5  TP  [TPTH-ANELLO-1MM]
sheet 04 COMET METROLOGY
C29  10NF  [0603]
C30  4.7NF  [0603]
C31  4.7NF  [0603]
C32  22NF  [0603]
C33  10NF  [0603]
CP3  NP  [0.5x1mm size]
H1  HOLE-2  [TPSMD-40RD]
H2  HOLE-2  [TPSMD-40RD]
H3  HOLE-2  [TPSMD-40RD]
J37  8191-7  [MORSV-508-2P]
N14  TP  [TPSMD-40RD]
N15  TP  [TPSMD-40RD]
N16  TP  [TPSMD-40RD]
N17  TP  [TPSMD-40RD]
N18  TP  [TPSMD-40RD]
N19  TP  [TPSMD-40RD]
N49  TP  [TPSMD-40RD]
N50  TP  [TPSMD-40RD]
R34  NP  [0204_Mini-MELF]
R35  NP  [0204_Mini-MELF]
R36  270K  [0204_Mini-MELF]
R37  NP  [0204_Mini-MELF]
R38  270K  [0204_Mini-MELF]
R39  1.00K  [0603]
R40  240K  [0204_Mini-MELF]
R41  NP  [0204_Mini-MELF]
R42  0.3mR
R43  1.00K  [0603]
R44  470R  [0204_Mini-MELF]
R45  1.00K  [0603]
R46  6.8R  [0204_Mini-MELF]
R48  1.00K  [0603]
R50  0R  [0603]
T2  T60404-E4626-X002
U1  IC-STCOMET10  [TQFP176  0.4picth 20*20]  (sections A,B,C,D,E,F,G,H,I,J,K)
sheet 05 LINE BREAKER
C34  100NF  [0603]
C35  100NF  [0603]
C36  10UF  [1206]
J5  HEADER 4
N20  TP  [TPSMD-40RD]
N21  TP  [TPSMD-40RD]
N22  TP  [TPSMD-40RD]
N23  TP  [TPSMD-40RD]
R47  0R  [0603]
R49  0R  [0603]
R51  47K  [0603]
R52  0R  [0603]
U2  L2293Q  [VFQFPN 5x5x1.0 32L]
sheet 06 POWER SUPPLY
BT1  CR-2032/BN
C37  100NF  [0402]
C38  2.2UF  [0603]
C39  10UF  [1206]
CN1  42376 / 22-28-6030 central pin#2 removed  [CON-MOLEX-42376-90-3]
CP1  NP  [1812 size]
CP2  NP  [1812 size]
D13  STTH102A  [SMA]
DL1  RED  [LEDC-0603]
DL2  RED  [LEDC-0603]
DL3  RED  [LEDC-0603]
F1  4A
J6  MKDS 1,5/ 2-5,08  [5.08]
J7  NEB 21 R  [DCJACK21MM-RS-448-382]
J8  CLOSE  [22-28-4023]
J9  CLOSE 3-2  [22-28-4033]
J10  CLOSE 3-2  [22-28-4033]
J11  CLOSE  [22-28-4023]
J13  42376 / 22-28-6040  [CON-MOLEX-42376-H-4]
J15  CLOSE  [22-28-4023]
J24  56000001009
J26  3003
J27  JUMPER 2.54  [JUMP254P-M-2]
J28  JUMPER 2.54  [JUMP254P-M-2]
J29  JUMPER 2.54  [JUMP254P-M-2]
J30  JUMPER 2.54  [JUMP254P-M-2]
J31  JUMPER 2.54  [JUMP254P-M-2]
L3  BLM31PG330SN1
L4  BLM31PG330SN1
L5  BLM31PG330SN1
N24  TP  [TPSMD-40RD]
N25  TP  [TPSMD-40RD]
N26  TP  [TPSMD-40RD]
N27  TP  [TPSMD-40RD]
N28  TP  [TPSMD-40RD]
N29  TP  [TPSMD-40RD]
N30  TP  [TPSMD-40RD]
N31  TP  [TPSMD-40RD]
N32  TP  [TPSMD-40RD]
N33  TP  [TPSMD-40RD]
N35  TP  [TPSMD-40RD]
N36  TP  [TPSMD-40RD]
N37  TP  [TPSMD-40RD]
R55  0R  [0603]
R56  NP  [0805]
R57  75R  [2010]
R58  75R  [2010]
R59  22K  [0603]
R60  4.7K  [0603]
R61  2.2K  [0603]
R208  NP  [0603]
TP6  KEYSTONE-5000  [KEYSTONE5000]
TP7  TP  [TPTH-PERNO-13MM]
TP8  TP  [TPTH-PERNO-13MM]
TP9  TP  [TPTH-PERNO-13MM]
TP10  TP  [TPTH-PERNO-13MM]
U3  L4931CDT33  [DPAK(TO-252)]
sheet 07 COMET POWER SUPPLY
C40  10UF  [1206]
C41  100NF  [0603]
C42  100NF  [0603]
C43  10UF  [1206]
C44  100NF  [0402]
C45  10UF  [0805]
C46  10UF  [0805]
C47  1UF  [0603]
C48  100NF  [0402]
C49  100NF  [0402]
C50  100NF  [0402]
C51  10UF  [0805]
C52  100NF  [0402]
C53  10UF  [0805]
C54  10UF  [0805]
C55  100NF  [0402]
C56  100NF  [0402]
C57  100NF  [0402]
C58  NP  [0805]
C59  100NF  [0402]
C60  NP  [0805]
C61  100NF  [0402]
C62  NP  [0805]
C63  100NF  [0402]
C64  10UF  [0805]
C65  100NF  [0402]
C66  10UF  [0805]
C67  100NF  [0402]
C68  10UF  [0805]
C69  10UF  [0805]
C70  100NF  [0402]
C71  100NF  [0402]
C72  100NF  [0402]
C73  100NF  [0402]
C74  100NF  [0402]
C75  100NF  [0402]
C76  100NF  [0402]
C77  100NF  [0402]
C78  100NF  [0402]
C79  100NF  [0402]
C80  100NF  [0402]
C81  100NF  [0402]
C82  100NF  [0402]
C83  47PF  [0402]
C118  10UF  [0805]
D14  NP  [SOD323]
FB1  BLM18AG331SN1D  [0603]
FB2  BLM18AG331SN1D  [0603]
J16  OPEN  [22-28-4023]
JP10  SHORT  [JP2SO]
N34  TP  [TPSMD-40RD]
N38  TP  [TPSMD-40RD]
R62  0R  [0603]
R63  NP  [0603]

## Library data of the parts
M1 M3 M5 M6 M8 M9 = HOLE
M2 M4 M7 = OPTICAL_TARGET
M10-M15 = COLUMN_FF2: Column NYLON; M3; L=12mm; Distributor: ADEX; Manufacturer: ACCEL ENISO; Manufacturer Part Number: ENISO-A3050-E1-12; Part Number: ENISO-A3050-E1-12; Datasheet: http://www.accel.fr/articles.php?lng=fr&pg=16
M16-M19 = COLUMN_MF2: Column BRASS; M3; L1=5mm; L2=5mm; Distributor: ADEX; Manufacturer: BOSSARD; Manufacturer Part Number: BN3321.1385119; Part Number: BN3321.1385119; Datasheet: https://us.shop.bossard.com/fr/index.cfm?app_page=0:31008:30002:9835:3&search_text=3321:%20:%20:
M20-M25 = SCREW_3: SCREW; NYLON; M3; L=4mm; Distributor: ADEX; Manufacturer: BOSSARD; Manufacturer Part Number: BN1061.1401165; Part Number: BN1061.1401165; Datasheet: https://us.shop.bossard.com/fr/index.cfm?app_page=0:31008:30002:9808:3&search_text=1061:%20:%20:
C1 C17 = CAP_NP: CAP CER 27pF 50V  COG 0603; Manufacturer: MURATA; Manufacturer Part Number: GRM1885C1H270JA01D; PSpice: C; Package_Type: C0603; Part Number: GRM1885C1H270JA01D; Part Type: CERAMIC; Tolerance: 5%; Voltage: 50V; Datasheet: http://docs-europe.electrocomponents.com/webdocs/0873/0900766b808736db.pdf
C2 C18 = CAP_NP: CAP CER 4.7pF 50V COG 0603; Manufacturer: MURATA; Manufacturer Part Number: GRM1885C1H4R7CZ01D; PSpice: C; Package_Type: C0603; Part Number: GRM1885C1H4R7CZ01D; Part Type: CERAMIC; Tolerance: 5%; Voltage: 50V; Datasheet: http://docs-europe.electrocomponents.com/webdocs/0873/0900766b808736db.pdf
C3-C5 C8 C13-C16 C27 C28 C34 C35 C41 C42 = CAP_NP: CAP CER 100nF 50V X7R 0603; Manufacturer: MURATA; Manufacturer Part Number: GRM188R71H104KA93D; PSpice: C; Package_Type: C0603; Part Number: GRM188R71H104KA93D; Part Type: CERAMIC; Tolerance: 5%; Voltage: 50V; Datasheet: http://www.farnell.com/datasheets/1692833.pdf
C6 C10 = CAP_NP: CAP CER 1µF 25V X5R 0805; Manufacturer: KEMET; Manufacturer Part Number: C0805C105K3PACTU; PSpice: C; Package_Type: C0805; Part Number: C0805C105K3PACTU; Part Type: CERAMIC; Tolerance: 10%; Voltage: 25V
C7 C12 = CAP_NP: CAP CER 22µF 25V X5R 1206; Manufacturer: MURATA; Manufacturer Part Number: GRM31CR61E226KE15L; PSpice: C; Package_Type: C1206; Part Number: GRM31CR61E226KE15L; Part Type: CERAMIC; Tolerance: 10%; Voltage: 25V
C21 C121 C122 = CAP_NP: CAP NP 0402; PSpice: C; Package_Type: C0402; Part Number: C_NP_0402
D1-D4 = DIODE_SCHOTTKY21: Power Schottky LOW DROP POWER SCHOTTKY RECTIFIER; ActivepartsID: http://CDS2.ORCAD.COM/default.asp?PID=2147075; ICA_MFR_NAME: ST MICRO; ICA_PARTNUM: $$2147075$$STPS1L30A; Manufacturer: STMICROELECTRONICS; Package_Type: DIODE-STPS1L30A; Datasheet: http://www.st.com/st-web-ui/static/active/en/resource/technical/document/datasheet/CD00001323.pdf
J1-J4 J8 J11 J15 = JUMP254P-M-2: Manufacturer: MOLEX; Package_Type: JUMPER-CLOSE; Part Number: 22-28-4023_C; Datasheet: http://www.molex.com/pdm_docs/sd/022284023_sd.pdf
J27-J35 = JUMP-Female-2P-MetalContact: JUMPER FEMALE METAL CONTACT; Distributor: RS; Distributor Part Number: 481-0738; Manufacturer: KONTEL; Manufacturer Part Number: ETAME 3131730000430; Datasheet: http://de.rs-online.com/web/p/jumper-und-shunts/4810738/
JP1 JP2 JP8 JP10 = JP2SO-SHORT: Solder Bridge with Copper Short; Part Number: Solder Bridge SHORT
N1-N38 N49 N50 = NEEDLE_PAD: Pad 1.7mm for test needle; Package_Type: TPSMD-1.7MM; Part Number: NEEDLE-PAD-1.7mm
R1 R15 = R: RESISTOR,  2.00K OHM 1/16W 1% 0603 SMD; ActivepartsID: http://CDS2.ORCAD.COM/default.asp?PID=1784369; ICA_MFR_NAME: PANASONIC CORP; ICA_PARTNUM: $$1784369$$ERJ-3EKF2001V; Manufacturer: PANASONIC CORP; Manufacturer Part Number: ERJ-3EKF2001V; Package_Type: R0603; Part Number: ERJ-3EKF2001V; Part type: CMS; Power: 1/16W; Tolerance: 1%; Datasheet: http://www.panasonic.com/industrial_oem/electronic_components/pdf/erj_precision.pdf
R2 R16 = R: RESISTOR,  6.80K OHM 1/10W 1% 0603 SMD; Manufacturer: PANASONIC CORP; Manufacturer Part Number: ERJ-3EKF6801V; Package_Type: R0603; Part Number: ERJ-3EKF6801V; Part type: CMS; Power: 1/10W; Tolerance: 1%
R3 R4 R6 R7 R10 R11 R13 R14 R28 R51 = R: 47K OHM 1% 1/10W; Manufacturer: PANASONIC CORP; Manufacturer Part Number: ERJ-3EKF4702V; Package_Type: R0603; Part Number: ERJ-3EKF4702V; Part type: CMS; Power: 1/10W; Tolerance: 1%
R5 R12 R18 R19 R47 R49 R50 R52 R55 R62 = R: 0.0 OHM 5% 1/10W 0603; Manufacturer: YAGEO; Manufacturer Part Number: RC0603JR-070RL; Package_Type: R0603; Part Number: RC0603JR-070RL; Part type: CMS; Power: 1/10W; Tolerance: 5%
R8 R9 R56 = R: RES NP 0805; Package_Type: R0805; Part Number: R_NP_0805; Part type: CMS
C19 = CAP_NP: CAP PET 15nF 300VAC; Distributor: FARNELL; Distributor Part Number: 1854809; Manufacturer: PANASONIC; Manufacturer Part Number: ECQU3A153MG; PSpice: C; Package_Type: ECQU3A153MG; Part Number: ECQU3A153MG_NP; Part Type: FILM CAPACITOR; Tolerance: 20%; Voltage: 300VAC; Datasheet: http://www.farnell.com/datasheets/817039.pdf
C20 = CAP_NP: CAP PP 470nF 330VAC 265X100x165-P225; Distributor: FARNELL / RS; Distributor Part Number: 1781913  / 669-0107; Manufacturer: EPCOS B32913A3474M; Manufacturer Part Number: EPCOS B32913A3474M; PSpice: C; Package_Type: CAPP-26.5X10.0X16.5-P22.5_NC; Part Number: B32913A3474M; Part Type: FILM CAPACITOR; Tolerance: 20%; Voltage: 330VAC; Datasheet: http://www.farnell.com/datasheets/486609.pdf
C22-C26 C29 C33 = CAP_NP: CAP CER 10nF 25V X7R 0603; Manufacturer: AVX; Manufacturer Part Number: 06033C103KAT2A; PSpice: C; Package_Type: C0603; Part Number: 06033C103KAT2A; Part Type: CERAMIC; Tolerance: 10%; Voltage: 25V
C119 C120 = CAP_NP: CAP foot print in solderbridge 0603; PSpice: C; Package_Type: C0603; Part Number: C_CLOSE_0603; Part Type: NP
D5 = DIODE_BI-DIR_TRIG: DIODE DIAC; Package_Type: DIODE-SMB; Part Number: DIODE DIAC
D6 = DIODE_BI-DIR_TRIG: DIODE SM6T18CA - DIODE TVS SMB 600W 18V; Manufacturer: STMICROELECTRONICS; Package_Type: DIODE-SM6T18CA; Datasheet: http://fr.farnell.com/stmicroelectronics/sm6t18ca/diode-tvs-smb-600w-18v/dp/9802649?whydiditmatch=rel_3&matchedProduct=3573412&matchedProduct=3573412&whydiditmatch=rel_3
D7 D8 = DIODE_BI-DIR_TRIG: DIODE SM6T10CA - DIODE TVS 10V 600W BI SMB RL; Manufacturer: STMICROELECTRONICS; Package_Type: DIODE-SM6T6V8CA; Datasheet: http://fr.farnell.com/jsp/displayProduct.jsp?sku=9885854&CMP=KNC-GFR-FFR-GEN-SKU-MDC&mckv=szrtQwT0E|pcrid|20197391234|kword|sm6t10ca|match|p|plid|
D9 = DIODE_BI-DIR_TRIG: DIODE, TVS, SMAJ15CA, 15V, 20.6A, DO-214AB; ActivepartsID: http://CDS2.ORCAD.COM/default.asp?PID=2289191; ICA_MFR_NAME: MICROSEMI CORP; ICA_PARTNUM: $$2289191$$SMAJ15CA; Manufacturer: STMICROELECTRONICS; Voltage: 15V; Datasheet: http://www.microsemi.com/datasheets/msc0270a.pdf
D10 = DIODE: Ultrafast 600V TURBO 2 ULTRAFAST HIGH VOLTAGE RECTIFIER; ActivepartsID: http://CDS2.ORCAD.COM/default.asp?PID=2147727; Distributor: RS; Distributor Part Number: 485-8500; ICA_MFR_NAME: ST MICRO; ICA_PARTNUM: $$2147727$$STTH1L06A; Manufacturer: STMICROELECTRONICS; Package_Type: DIODE-STTH1L06A; Voltage: 600V; Datasheet: http://www.st.com/stonline/books/pdf/docs/8321.pdf
D11 = DIODE_ZENER: ZENER VOLTAGE REGULATOR 2.0 V 3V 200mW; Manufacturer: FAIRCHILD; Package_Type: SOD323; Datasheet: http://www.digikey.ca/product-detail/en/MM3Z3V0C/MM3Z3V0CCT-ND/1626880
ISO1 = OPTO_ISOLATOR-A_0: OPTOCOUPLEUR SORTIE TRANSISTOR VDE; Manufacturer: TOSHIBA; Manufacturer Part Number: TLP781(D4-GB.F); Package_type: TLP781GB; Part Number: TLP781
JP3-JP7 JP9 = JP2SO: Solder Bridge; Package_Type: SOLDER-BRIDGE; Part Number: Solder Bridge
L1 = INDUCTOR: INDUCTOR 15uH 4.1A; Manufacturer: WURTH ELEKTRONIK; Manufacturer Part Number: 7447714150; Package_Type: IND-EPCOS-B82464G4; Part Number: 7447714150; Tolerance: 20%; Datasheet: http://katalog.we-online.de/pbs/datasheet/7447714150.pdf
L2 = INDUCTOR: INDUCTOR 470uH 0.22A; Manufacturer: WURTH ELEKTRONIK; Manufacturer Part Number: 744045471; Part Number: 744045471; Tolerance: 30%; Datasheet: http://katalog.we-online.de/pbs/datasheet/744045471.pdf
L6 L7 = INDUCTOR: Manufacturer: WURTH ELEKTRONIK; Manufacturer Part Number: 744043151; Part Number: 744043151-CLOSE; Datasheet: http://katalog.we-online.de/pbs/datasheet/744042221.pdf
L8 = INDUCTOR: Manufacturer: WURTH ELEKTRONIK; Manufacturer Part Number: 744042221; Part Number: 744042221_NP; Datasheet: http://katalog.we-online.de/pbs/datasheet/744043151.pdf
R17 R207 = R: RES NP 1206; Package_Type: R1206; Part Number: R_NP_1206; Part type: CMS
R20 = R: RES 62 OHM 1% 1/10W; Manufacturer: PANASONIC CORP; Manufacturer Part Number: PAT***; Package_Type: R0603; Part Number: ERJ3EKF62R0V; Part type: CMS; Power: 1/10W; Tolerance: 1%
R21 R22 = R: RESISTOR,  49.9 OHM 1/16W 1% 0603 SMD; ActivepartsID: http://CDS2.ORCAD.COM/default.asp?PID=1784348; ICA_MFR_NAME: PANASONIC CORP; ICA_PARTNUM: $$1784348$$ERJ-3EKF49R9V; Manufacturer: PANASONIC CORP; Manufacturer Part Number: ERJ-3EKF49R9V; Package_Type: R0603; Part Number: ERJ-3EKF49R9V; Part type: CMS; Power: 1/16W; Tolerance: 1%; Datasheet: http://www.panasonic.com/industrial_oem/electronic_components/pdf/erj_precision.pdf
R23 R26 R27 = R: RES 33K OHM 1/4W 1% 1206; Manufacturer: PANASONIC CORP; Manufacturer Part Number: ERJ-8ENF3302V; Package_Type: R1206; Part Number: ERJ-8ENF3302V; Part type: CMS; Power: 1/4W; Tolerance: 1%
R24 R39 R43 R45 R48 = R: RESISTOR,  1.00K OHM 1/10W 1% 0603 SMD; ActivepartsID: http://CDS2.ORCAD.COM/default.asp?PID=1783654; ICA_MFR_NAME: PANASONIC CORP; ICA_PARTNUM: $$1783654$$ERJ-3EKF1001V; Manufacturer: PANASONIC CORP; Manufacturer Part Number: ERJ-3EKF1001V; Package_Type: R0603; Part Number: ERJ-3EKF1001V; Part type: CMS; Power: 1/10W; Tolerance: 1%; Datasheet: http://www.panasonic.com/industrial_oem/electronic_components/pdf/erj_precision.pdf
R25 = R: 100K OHM 5% 1/8W; Manufacturer: PANASONIC CORP; Manufacturer Part Number: ERJ6GEYJ104V; Package_Type: R0805; Part Number: ERJ6GEYJ104V; Part type: CMS; Power: 1/8W; Tolerance: 5%; Datasheet: http://www.farnell.com/datasheets/1500035.pdf
R29 = R: 10M OHM 5% 1/10W; Manufacturer: PANASONIC CORP; Manufacturer Part Number: ERJ3GEYJ106V; Package_Type: R0603; Part Number: ERJ3GEYJ106V; Part type: CMS; Power: 1/10W; Tolerance: 5%
R30 R31 = R: RES 220K OHM 1/4W 1% 1206 SMD; Manufacturer: PANASONIC CORP; Manufacturer Part Number: ERJ-8ENF2203V; Package_Type: R1206; Part Number: ERJ-8ENF2203V; Part type: CMS; Power: 1/4W; Tolerance: 1%
R32 R33 = R: 120M OHM 1% 1/10W; Package_Type: R0603; Part Number: 120R_1%_0603; Part type: CMS; Power: 1/10W; Tolerance: 1%
SIOV1 = SIOV-S14K320: VARISTOR S14K320; Distributor: RS; Distributor Part Number: 289-7216; Manufacturer: EPCOS; Part Number: S14K680; Datasheet: http://docs-europe.electrocomponents.com/webdocs/0188/0900766b80188ddb.pdf
T1 = TRAFO-TDK-SRW13EP: TRAFO-TDK-SRW13EP SRW13ES 1,0mH 25% TRANSFORMER leadfree; Manufacturer: TDK; Manufacturer Part Number: SRW13EP-X05H002; Package_Type: SRW13EP-X05H002; Part Number: SRW13EP-X05H002; Datasheet: \\rnx003a.rns.st.com\EMEA\0-SHARED\3-Datasheet\PLC-Power_Line_Communication\Transformator\TDK\SRW13EP-X05H002 13.12.2007.pdf
T1-2 = TRAFO-TDK-SRW13EP-X07S002: SMD TRAFO-WE-750-510-231; Manufacturer: WURTH ELEKTRONIK; Manufacturer Part Number: WE-750-510-231; Part Number: WE-750-510-231
TP1-TP5 = TPTH-ANELLO-1MM: Point Test TPTH-ANELLO-1MM black; Distributor: FARNELL; Distributor Part Number: 1463077; Manufacturer: KEYSTONE; Manufacturer Part Number: 534-5001; Datasheet: http://fr.farnell.com/keystone/5001/test-point-connector-black/dp/1463077?Ntt=534-5001
C30 C31 = CAP_NP: CAP CER 4.7nF 50V X7R 0603; Distributor: Farnell; Distributor Part Number: 7569530; Manufacturer: AVX; Manufacturer Part Number: 06035C472KAZ2A; PSpice: C; Package_Type: C0603; Part Number: 06035C472KAZ2A; Part Type: CERAMIC; Tolerance: 10%; Voltage: 50V
C32 = CAP_NP: CAP CER 22nF 50V X7R 0603; Manufacturer: AVX; Manufacturer Part Number: 06035C223JAT2A; PSpice: C; Package_Type: C0603; Part Number: 06035C223JAT2A; Part Type: CERAMIC; Tolerance: 5%; Voltage: 50V
CP3 = COPPER_PAD: Copper for GNDs connection; Package_Type: COPPER1005mm; Part Number: Copper 1005mm
H1 H2 = HOLE-2: Metal Hole 1mm; Package_Type: TP-1MM; Part Number: Hole-1mm
H3 = HOLE-2: Metal Hole 2mm; Package_Type: TP-2MM; Part Number: Hole-2mm
J37 = KEYSTONE_8191_7: SCREW CONNECTOR one pole; Distributor: RS; Distributor Part Number: 481-4027; Manufacturer: Keystone; Package_Type: KEY8191; Datasheet: http://docs-europe.electrocomponents.com/webdocs/0404/0900766b804043be.pdf
R34 R35 R37 R41 = R: RES NP 0204-Mini-MELF; Part Number: R_NP_0204-Mini-MELF; Part type: CMS; Datasheet: http://www.vishay.com/docs/20004/smm0204.pdf
R36 R38 = R: RES 270K OHM 1% 50ppm/K 1/4W SMD; Part Number: 270K_1%_50ppm/K_0204-Mini-MELF; Part type: CMS; Power: 1/4W; Tolerance: 1%; Datasheet: http://www.vishay.com/docs/20004/smm0204.pdf
R40 = R: RES 240K OHM 1% 50ppm/K 1/4W SMD; Part Number: 240K_1%_50ppm/K_0204-Mini-MELF; Part type: CMS; Power: 1/4W; Tolerance: 1%; Datasheet: http://www.vishay.com/docs/20004/smm0204.pdf
R42 = R_0_SHUNT: SHUNT-BKW-M Equiped-0.3 mOhm; Manufacturer: Isabellenhutte; Manufacturer Part Number: BKW-M-R0003-5.0; Package_Type: SHUNT-BKW-M; Part Number: SHUNT-BKW-M P; Part type: Through Holes; Datasheet: http://www.datasheets360.com/pdf/8502076975055306148?comp=4939
R44 = R: RES 470 OHM 1% 50ppm/K 1/4W SMD; Part Number: 470R_1%_50ppm/K_0204-Mini-MELF; Part type: CMS; Power: 1/4W; Tolerance: 1%; Datasheet: http://www.vishay.com/docs/20004/smm0204.pdf
R46 = R: RES 6.8 OHM 1% 50ppm/K 1/4W SMD; Part Number: 6.8R_1%_50ppm/K_0204-Mini-MELF; Part type: CMS; Power: 1/4W; Tolerance: 1%; Datasheet: http://www.vishay.com/docs/20004/smm0204.pdf
T2 = TRANSFO-CURRENT_FLYING_KIT: Current Transformer; Manufacturer: VACUUMSCHMELZE; Datasheet: http://www.vacuumschmelze.com/fileadmin/documents/pdf/kbproduktblaetter/4626-X002.pdf
U1 = IC-COMET10: Manufacturer: STMICROELECTRONICS; Package_Type: COMET10
C36 = CAP_NP: CAP CER 10µF 50V X5R 1206; PSpice: C; Package_Type: C1206; Part Number: 10UF_50V_X5R_1206; Part Type: CERAMIC; Tolerance: 10%; Voltage: 50V
J5 = HEADER_4: CONN,HDR,W/ FRIC LCK,4P,2.54MM; Distributor: RS; Distributor Part Number: 483-8483; ICA_MFR_NAME: MOLEX; ICA_PARTNUM: $$1188253$$22-27-2041; Manufacturer: MOLEX; Manufacturer Part Number: 22-27-2041; Package_Type: CON-22-27-2041; Part Number: 22-27-2041; Datasheet: http://docs-europe.electrocomponents.com/webdocs/0462/0900766b80462714.pdf
U2 = L2293Q: Push-pull four channel driver with diodes; Distributor: RS; Distributor Part Number: 687-5380; Manufacturer: STMICROELECTRONICS; Datasheet: http://www.st.com/st-web-ui/static/active/en/resource/technical/document/datasheet/CD00204113.pdf
BT1 = BATTERY-KIT: BATTERY CR2032 LITHIUM 3V 180mAH; Distributor: RS; Distributor Part Number: 908654; Manufacturer: PANASONIC CORP; Package_type: BAT_HOLDER_3003; Datasheet: http://www.farnell.com/datasheets/15138.pdf
C37 C44 C48-C50 C52 C55-C57 C59 C61 C63 C65 C67 C70-C82 = CAP_NP: CAP CER 100nF 16V X7R 0402; Manufacturer: MURATA; Manufacturer Part Number: GRM155R71C104KA88D; PSpice: C; Package_Type: C0402; Part Number: GRM155R71C104KA88D; Part Type: CERAMIC; Tolerance: 10%; Voltage: 16V
C38 = CAP_NP: CAP CER 2.2uF 6.3V X7R; PSpice: C; Package_Type: C0603; Part Number: 2.2UF_6.3V_X7R_0603; Part Type: CERAMIC; Tolerance: 20%; Voltage: 6.3V
C39 C40 C43 = CAP_NP: CAP CER 10µF 25V X5R 1206; Distributor: Farnell; Distributor Part Number: 1828816; Manufacturer: MURATA; Manufacturer Part Number: GRM31CR61E106KA12L; PSpice: C; Package_Type: C1206; Part Number: GRM31CR61E106KA12L; Part Type: CERAMIC; Tolerance: 10%; Voltage: 25V
CN1 = CON-MOLEX-KK100-3P_2pins: CON 3P edge 2.54m Molex series 42376 with centered pin removed by EMS; Manufacturer: MOLEX; Manufacturer Part Number: 22-28-6030; Package_Type: CON-MOLEX-42376-H-3_2PINS; Part Number: 22-28-6030 2 pins; Datasheet: http://www.molex.com/molex/products/datasheet.jsp?part=active/0022286030_PCB_HEADERS.xml
CP1 CP2 = COPPER_PAD: Copper for GNDs connection; Package_Type: COPPER1812; Part Number: Copper 1812
D13 = DIODE: High efficiency Ultra Fast Diode; Distributor: RS; Distributor Part Number: 485-8465; Manufacturer: STMICROELECTRONICS; Package_Type: DIODE-STTH102A; Voltage: 200V; Datasheet: http://www.st.com/web/en/resource/technical/document/datasheet/CD00002613.pdf
DL1-DL3 = LED: RED LEDC-0603; Distributor: RS; Distributor Part Number: 692-1041; Manufacturer: LITE-ON; Manufacturer Part Number: LTST-C193KRKT-5A; Package_Type: LEDC-0603_RED; Part Number: LED_RED_0603_2mA; Datasheet: http://docs-europe.electrocomponents.com/webdocs/0dc0/0900766b80dc0551.pdf
F1 = FUSE_KIT: MCMET 4A MULTICOMP; Distributor: Farnell; Distributor Part Number: 1566078; Manufacturer: MULTICOMP; Manufacturer Part Number: MCMET 4A MULTICOMP; Part Number: MCMET 4A MULTICOMP; Datasheet: http://uk.farnell.com/multicomp/mcmet-4a-250v/fuse-radial-slow-blow-4a/dp/1566078
J6 = MORSV-508-2P: Screw connector 2 poles; Distributor: RS; Distributor Part Number: 467-0350; Manufacturer: PHOENIX CONTACT; Package_Type: MKDS1.5/2-5.08; Voltage: 320V; Datasheet: http://docs-europe.electrocomponents.com/webdocs/0e7d/0900766b80e7dc97.pdf
J7 = DCJACK21MM-RS-448-382: DCJACK21MM; Distributor: RS; Distributor Part Number: RS-448-382; Manufacturer: Lumberg; Datasheet: http://docs-europe.electrocomponents.com/webdocs/0569/0900766b805694d6.pdf
J9 J10 = JUMP254P-M-3: Manufacturer: MOLEX; Package_Type: JUMPER-3-CLOSE3_2; Part Number: 22-28-4033_C23
J13 = CONN_PLUG_4: CON 4P edge 2.54m Molex series 42376; Manufacturer: MOLEX; Manufacturer Part Number: 22-28-6040; Part Number: 22-28-6040; Datasheet: http://www.molex.com/molex/products/datasheet.jsp?part=active/0022286040_PCB_HEADERS.xml
J24 = FUSEHOLDER: Radial Lead Micro Fuseholder; Distributor: FARNELL; Distributor Part Number: 1185363; Manufacturer: LITTELFUSE; Package_Type: FUSE-HOLDER-56000001009; Voltage: 250V; Datasheet: http://www.farnell.com/datasheets/1685543.pdf
J26 = BATTERY-HOLDER: HOLDER BATT SMD CR2032; Distributor: Farnell; Distributor Part Number: 908654; Manufacturer: KEYSTONE; Package_type: BAT_HOLDER_3003; Datasheet: http://www.farnell.com/datasheets/15138.pdf
L3-L5 = INDUCTOR: Manufacturer: MURATA; Package_Type: L1206
R57 R58 = R: 75 OHM 1% 0.75W; Distributor: RS; Distributor Part Number: 1887589RL; Manufacturer: MULTICOMP; Manufacturer Part Number: MCPWR10FTEQ0750; Package_Type: R2010; Part Number: MCPWR10FTEQ0750; Part type: CMS; Power: 3/4W; Tolerance: 1%; Datasheet: http://www.farnell.com/datasheets/1718729.pdf
R59 = R: RES 22KOHM 1/10W 5% 0603 SMD; Package_Type: R0603; Part Number: 22K_5%_0603; Part type: CMS; Power: 1/10W; Tolerance: 5%
R60 = R: RES 4.7K OHM 5% 1/10W 0603 SMD; Package_Type: R0603; Part Number: 4.7K_5%_0603; Part type: CMS; Power: 1/10W; Tolerance: 5%
R61 = R: RES 2.2KOHM 1/10W 5% 0603 SMD; Package_Type: R0603; Part Number: 2.2K_5%_0603; Part type: CMS; Power: 1/10W; Tolerance: 5%
R63 R208 = R: RES NP 0603; Package_Type: R0603; Part Number: R_NP_0603; Part type: CMS
TP6 = TEST_POINT: TEST POINT RED; Distributor: FARNELL; Distributor Part Number: 1463076; Manufacturer: KEYSTONE; Manufacturer Part Number: KEYSTONE 5000; Part Number: KEYSTONE 5000; Datasheet: http://www.keyelco.com/category.cfm/keyelco/Terminals-Terminal-Boards/id/509
TP7-TP10 = TPTH-PERNO-13MM: Point Test CONN 1x1 TPTH-PERNO-13MM; Manufacturer: Distrelec; Manufacturer Part Number: 450400; Datasheet: https://www.distrelec.ch/ishopWebFront/search/luceneSearch.do?dispatch=find&keywordPhrase=450400+
U3 = L4931A_DPAK: VERY LOW DROP VOLTAGE REGULATOR WITH INHIBIT; ActivepartsID: http://CDS2.ORCAD.COM/default.asp?PID=2045696; Distributor: RS; Distributor Part Number: 355-3490; ICA_MFR_NAME: STMICROELECTRONICS; ICA_PARTNUM: $$2045696$$L4931CDT33; Manufacturer: STMICROELECTRONICS; Package_Type: L4931XX; Datasheet: http://www.st.com/st-web-ui/static/active/en/resource/technical/document/datasheet/CD00000971.pdf
C45 C46 C51 C53 C54 C64 C66 C68 C69 C118 = CAP_NP: CAP CER 10µF 10V X7R 0805; Distributor: FARNELL; Distributor Part Number: 1828828; Manufacturer: MURATA; Manufacturer Part Number: GRM21BR71A106KE51L; PSpice: C; Package_Type: C0805; Part Number: GRM21BR71A106KE51L; Part Type: CERAMIC; Tolerance: 10%; Voltage: 10V
C47 = CAP_NP: CAP CER 1UF 10V X7R 0603; PSpice: C; Package_Type: C0603; Part Number: 1UF_10V_X7R_0603; Part Type: CERAMIC; Tolerance: 15%; Voltage: 10V
C58 C60 C62 = CAP_NP: CAP NP 0805; PSpice: C; Package_Type: C0805; Part Number: C_NP_0805
C83 = CAP_NP: CAP CER 47PF 6V3 X5R 0402; PSpice: C; Package_Type: C0402; Part Number: 47PF_6V3_X5R_0402; Part Type: CERAMIC; Tolerance: 15%; Voltage: 6.3V
D14 = DIODE_SCHOTTKY: Small Signal Schottky diode; Distributor: RS; Distributor Part Number: 497-6557; Manufacturer: STMICROELECTRONICS; Manufacturer Part Number: BAT54J; Package_Type: DIODE-BAT54J; Part Number: BAT54J; Datasheet: http://docs-europe.electrocomponents.com/webdocs/0608/0900766b80608cc1.pdf
FB1 FB2 = INDUCTOR: FERRITE BEAD,330 OHM,0603; Manufacturer: MURATA; Package_Type: L0603; Tolerance: 25%
J16 = JUMP254P-M-2: Manufacturer: MOLEX; Package_Type: JUMPER-OPEN; Part Number: 22-28-4023_O; Datasheet: http://www.molex.com/pdm_docs/sd/022284023_sd.pdf

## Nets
1V2: C65.1 C66.1 C79.1 C80.1 N38.1 R63.2 TP6.1 U1.12(DVDD_1V2_FLASH) U1.23(DVDD_1V2__MCLK) U1.28(DVDD_1V2_1) U1.29(DVDD_1V2_QFS)
3V3: C69.1 C70.1 C71.1 C72.1 C73.1 C74.1 C75.1 C76.1 C77.1 C78.1 C81.1 C82.1 C83.1 C118.1 FB2.1 JP10.1 L3.2 N29.1 R62.2 R208.1 U1.4(DVDD_3V3_IO_1) U1.14(DVDD_3V3_FLASH) U1.24(DVDD_3V3_IO_2) U1.30(DVDD_3V3_QFS) U1.63(DVDD_3V3_IO_3) U1.83(DVDD_3V3_IO_4) U1.99(DVDD_3V3_IO_5) U1.130(DVDD_3V3_IO_6) U1.135(DVDD_3V3_IO_7) U1.154(DVDD_3V3_IO_8) U1.175(DVDD_3V3_IO_9) ; also on sheet 8
3V3_AUX: J8.2 N27.1 R24.1 ; also on sheet 8 10 11 12
3V3_JACK: C38.1 J9.1 N25.1 U3.3(VOUT)
3V3_PSU: J8.1 J9.2 J11.1 N28.1 R61.1
5V: C49.1 C50.1 C51.1 C52.1 C53.1 D14.1(ANODE) J16.2 L5.2 N33.1 U1.32(AVDD_5V_PGA) U1.38(AVDD_5V__RXADC) U1.58(AVDD_5V_TXDRV)
5V_PSU: J15.2 L5.1 N32.1 R60.1 ; also on sheet 10
GND_EARTH: C30.2 C31.1 C47.2 C56.2 CP2.1 CP3.1 N35.1 R42.3 R50.1 TP7.1 U1.85(METR_AGND_REG) U1.87(METR_AGND) U1.95(METR_GND_ESD)
GND_POWER: C3.2 C4.2 C5.1 C6.2 C10.2 C13.2 C14.2 C16.1 C21.1 C23.2 C25.1 C28.1 C37.2 C38.2 C39.2 C40.2 C41.2 C42.2 C43.2 C44.2 C45.2 C46.2 C49.2 C50.2 C51.2 C52.2 C53.2 C54.2 C55.2 C121.1 C122.1 CP1.1 CP2.2 D2.2(A) D4.2(A) D7.1 D8.1 D11.2(ANODE) DL1.1(CATHODE) DL2.1(CATHODE) DL3.1(CATHODE) J7.2 J7.3 J13.2 JP4.1 JP5.1 JP6.1 JP7.1 N36.1 R6.2 R7.2 R13.2 R14.2 R20.1 R28.1 R29.1 R32.1 R33.1 TP9.1 U1.35(AGND_1) U1.37(AGND_2) U1.40(PGND_2) U1.45(PGND_1) U1.51(AGND_5) U1.55(AGND_3) U1.60(AGND_4) U3.4(GND) ; also on sheet 8
GND_SIGNAL: C34.1 C35.1 C36.1 C48.2 C57.2 C58.2 C59.2 C60.2 C61.2 C62.2 C63.2 C64.2 C65.2 C66.2 C67.2 C68.2 C69.2 C70.2 C71.2 C72.2 C73.2 C74.2 C75.2 C76.2 C77.2 C78.2 C79.2 C80.2 C81.2 C82.2 C83.2 C118.2 CP1.2 J5.4 J26.2(-) N23.1 N37.1 TP8.1 TP10.1 U1.13(DGND_2) U1.31(DGND_1) U1.177(EXPAD) U2.1(NC(2)) U2.2(NC(1)) U2.3(NC(1)) U2.4(NC(1)) U2.5(NC(1)) U2.6(NC(1)) U2.7(NC(1)) U2.8(NC(1)) U2.9(GND) U2.17(GND) U2.18(NC(2)) U2.19(NC(2)) U2.20(NC(2)) U2.21(NC(2)) U2.22(NC(2)) U2.23(NC(2)) U2.24(GND) U2.28(GND) U2.32(GND) U2.33(CASE) ; also on sheet 8 10 11 12
VBAT: N24.1 R55.2 R208.2 U1.98(VBAT) ; also on sheet 10
VCC: C3.1 C4.1 C6.1 C10.1 C13.1 C14.1 C40.1 C41.1 C42.1 C43.1 D1.1(K) D3.1(K) L4.2 N31.1 R3.1 R4.1 R10.1 R11.1 U1.39(PVCC_1) U1.46(PVCC_2)
VCC_JACK: C39.1 D13.1(K) J10.1 R56.2 R57.2 R58.2
VCC_PSU: J10.2 L4.1 N30.1 R59.1 ; also on sheet 10
GPIO00_0: R49.2 ; also on sheet 9 10
GPIO00_1: R47.2 ; also on sheet 9 10
L_LOAD_METR: N14.1 R39.1 R42.1
L_METR: C32.2 CP3.2 N17.1 R44.1 U1.93(METR_VN)
L_PLC: CN1.1 D6.1 D10.2(A) J24.2 N4.1 SIOV1.1 T1.1 T1-2.8
N_PLC: C19.2 C20.2 CN1.3 J6.1 N3.1 R26.2 SIOV1.2
N_ZC_UNINSULATED: J37.1 J37.2 J37.3 J37.4 N49.1 R36.2 R207.1
PA1_INN: C17.1 C18.2 R15.1 R16.2 U1.47(PA1_INN)
PA1_INP: C122.2 R12.1 U1.48(PA1_INP)
PA1_OUT: C18.1 J3.1 N2.1 R11.2 R14.1 R16.1 U1.43(PA1_OUT_1) U1.44(PA1_OUT_2)
PA2_INN: C1.1 C2.2 R1.1 R2.2 U1.50(PA2_INN)
PA2_INP: C121.2 R5.1 U1.49(PA2_INP)
PA2_OUT: C2.1 J1.1 N1.1 R2.1 R3.2 R7.1 U1.41(PA2_OUT_1) U1.42(PA2_OUT_2)
PRI: JP3.1 L1.1 T1.4 T1-2.5
RELAY_A: J5.2 N21.1 U2.25(OUT4) U2.31(OUT1)
RELAY_B: J5.1 N20.1 U2.10(OUT2) U2.16(OUT3)
RX_INN: C22.1 N9.1 TP2.1 U1.33(RX_INN)
RX_INP: C26.1 N8.1 TP3.1 U1.34(RX_INP)
TRANSFORMER_1_S1: D5.1 D8.2 JP2.2 JP5.2 R17.2 R19.2 T1.10 T1-2.1
TRANSFORMER_1_S2: D5.2 D7.2 JP1.2 JP4.2 R17.1 R18.2 T1.7 T1-2.4
TX+: J4.1 N6.1 U1.56(TXDRV_OUTP)
TX-: J2.1 N10.1 U1.57(TXDRV_OUTN)
V_RELAY: C34.2 C36.2 J5.3 N22.1 R51.1 R52.1 U2.12(VS) U2.13(VS)
VCM1: C15.1 R10.2 R12.2 R13.1
VCM2: C8.1 R4.2 R5.2 R6.1
ZC_IN: JP8.1 JP9.2 N13.1 TP1.1 U1.36(ZC_IN)
N19662624: C19.1 C20.1 D6.2 JP3.2 L1.2
N19668823: C24.2 D9.2 JP6.2 L2.1 L7.2 R21.2
N19668825: C24.1 D9.1 JP7.2 L2.2 L6.2 R22.2
N19677666: N12.1 R32.2 TP4.1 U1.61(DAC_OUTP)
N19677670: N11.1 R33.2 TP5.1 U1.62(DAC_OUTN)
N19678321: C27.2 ISO1.3(EMITTER) R28.2
N19678343: R26.1 R27.2
N19678376: ISO1.1(ANODE) N5.1 R23.1 R25.2
N19678380: ISO1.2(CATHODE) N7.1 R25.1 R27.1
N19678382: C28.2 ISO1.4(COLLECTOR) R24.2
N19678384: C27.1 JP8.2 R29.2
N19681696: R30.1 R31.2
N19687904: C25.2 C26.2 C120.1 L8.2
N19688381: C44.1 C45.1 C46.1 D14.2(CATHODE) J16.1 N34.1 U1.53(AVDD_5V)
N19689219: C54.1 C55.1 FB2.2 U1.59(AVDD_3V3_DAC)
N19697609: C67.1 C68.1 U1.152(DVDD_1V2_3)
N19697625: C63.1 C64.1 U1.73(DVDD_1V2_2)
N19700823: C57.1 C58.1 C59.1 C60.1 C61.1 C62.1 R62.1 R63.1 U1.27(DVDD_3V3_REG_1) U1.72(DVDD_3V3_REG_2) U1.153(DVDD_3V3_REG_3)
N19703278: C48.1 FB1.2 U1.84(METR_AVDD_3V3)
N19703645: FB1.1 JP10.2
N19729807: C56.1 U1.88(METR_VREF)
N19730521: C47.1 U1.86(METR_AVDD_3V0)
N19734592: R36.1 R38.2
N19734595: R38.1 R40.2
N19734598: C32.1 N15.1 R40.1 R44.2 U1.94(METR_VP)
N19738569: C29.2 C31.2 R43.2 U1.92(METR_IN)
N19738577: C29.1 C30.1 R39.2 U1.91(METR_IP)
N20051895: DL3.2(ANODE) R61.2
N20056699: DL2.2(ANODE) R60.2
N20058352: C12.1 D3.2(A) D4.1(K) J3.2 R9.2
N20058428: C12.2 JP2.1 R9.1
N20058517: C7.1 D1.2(A) D2.1(K) J1.2 R8.2
N20058539: C7.2 JP1.1 R8.1
N20059633: C16.2 C17.2 R15.2
N20059708: C1.2 C5.2 R1.2
N20117644: D11.1(CATHODE) JP9.1 R31.1
N20191464: C21.2 R20.2 U1.52(CSF)
N20191865: C22.2 C23.1 C119.1 L8.1
N20385923: N16.1 R42.2 R43.1
N20620687: C8.2 J2.2
N20621054: C15.2 J4.2
N20622289: R18.1 R21.1
N20622428: R19.1 R22.1
N20810285: J26.1(+) R55.1
N21544849: H2.1 N19.1 R46.1 R48.1 R50.2
N21544859: H1.1 N18.1 R45.1 R46.2
N21544881: C33.1 R41.1 R45.2 U1.89(METR_AP)
N21544946: C33.2 R48.2 U1.90(METR_AN)
N21678705: J9.3 J13.1
N21678759: J10.3 J13.3
N21678762: J13.4 J15.1
N21912776: H3.1 N50.1 R34.2
N21912778: R35.1 R37.2
N21912780: R34.1 R35.2
N21912897: R37.1 R41.2
N21925547: C37.1 R57.1 R58.1 U3.1(VIN)
N21955920: J11.2 L3.1
N21981857: DL1.2(ANODE) R59.2
N22019929: D13.2(A) J7.1 N26.1 R56.1
N22289134: J6.2 J24.1
N22290554: R49.1 U2.26(IN4) U2.30(IN1)
N22290560: R47.1 U2.11(IN2) U2.15(IN3)
N22290568: C35.2 R52.2 U2.27(VSS)
N22290757: R51.2 U2.14(EN2) U2.29(EN1)
N22381708: R30.2 R207.2
N22388340: C119.2 L6.1
N22388376: C120.2 L7.1
N22595768: D10.1(K) R23.2

Not connected (* = marked no-connect by the designer): M1 1*; M2 1*; M3 1*; M4 1*; M5 1*; M6 1*; M7 1*; M8 1*; M9 1*

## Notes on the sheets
sheet 1
- COMET10 EVAL Board
- Green = Serigraphy
- WARNING!
  HIGH  VOLTAGE
  ON  BOARD
- 1	 - 	Index
   	2	 - 	COMET Power Amplifier
   	3	 - 	COMET PLC coupling
   	4	 - 	COMET  Metrology
   	5	 - 	Line Breaker
   	6	 - 	Power Supply interface
   	7	 - 	COMET Power Supply
   	8	 - 	COMET SYSTEM
  	 9	 - 	COMET GPIOs
  	10	 - 	MODULE Connector
  	11	 - 	Serial Interfaces (UART,SPI FLASH, EEPROM) 1Leds
  	12	 - 	J-LINK OB JTAG
- DEMO BOARD ONLY
  FOR EVALUATION
  PURPOSE
- ST logo
- EVALSTCOMET-1
- PCBAA-REV3
- RoHS EU
- RoHS Chinese
- Revision History
- AA_COMET_EVB_MOTHER_BOARD_Rev531
sheet 2
- This 100nF can be removed if input R bridge cap
  is close to this output bridge
- -
- PA-
- TX-
- PA2
- +
- Closest to IC
- PA+
- This 100nF can be removed if input R bridge cap
  is close to this output bridge
- TX+
- +
- PA1
- -
- Power amplifier
- Closest to IC
sheet 3
- NOTE:
  both // caps below must be placed as double footprint
- NOTE:
  Solder bridge must be beside
  inductor (not below)
- !! Caution !!
  TP isolation
- SMD option :
- WE 750510682
  OR
- FCC option:
  Close Solder bridge JP3 remove L1
  Populate L6,L7 with 27uH
  Populate C23, C25, C119, C120 with 12nF (25V X7R)
  Populate C24 with 1.8nF (25V X7R)
  Populate L8 with 56uH and L2 with 150uH
- Through Holes Footprint options :
- OR
  TDK SRW13EP-X05H002
- Cenelec Default option:
  Open JP3
  Solder bridge L6,L7, C119, and C120
  L8 NP
- For Single ended
- Line driver power amplifier
- PLC coupling and RX filter
- ZCI: Zero Crossing ISOLATED coupling
- Zero crossing, RX input, DAC and pre-driver
- DAC+
- DAC-
- NOTE:
  Place parts above close to Main inputs
- ZC
- RX+
- RX-
- Optional
- Optional
- ZCNI: Zero Crossing
  NON-ISOLATED coupling
- NOTE:
  Place both resistor close to Main inputs
sheet 4
- Very important!! Connect
  N_ZC_UNINSULATED signal
  just at METROLOGY NEUTRAL input
  (STAR connection)
- 2ND  VOLT
- METR_AP can be used for 2nd Voltage measurement (after line Breaker),
  according to the following BOM modification:
  R34 = 620kOhm (1%, 50pm/K, 0204 mini-MELF)
  R35 = R37 = 470kOhm (1%, 50pm/K, 0204 mini-MELF)
  R41 = R45 = R48 = 0 Ohm
  R50 = 470 Ohm (1%, 50pm/K, 0204 mini-MELF)
  C33 = 22NF
- NEUTRAL-MET
- The shunt resistor shall be in the range of 0.1-5mOhm
  to avoid excessive power dissipation
  1mOhm@16A=0.25W
  2mOhm@16A=0.5W
  A typical shunt value for 60A meter is: 220uOhm, 5%, 50ppm/°C
  Shunt used below (SHUNT-BKW-M):
  Isabellenhutte 0.3mOhm 5% 20ppm BKW-M-R0003-5.0
- NEUTRAL NON-ISOLATED input
  (METR-ZCNI sections)
- Isabellenhutte BKW shunt:
  The AC LINE wires of mains HAVE to be connected directly on shunt holes
- LINE-LOAD
- LINE LOAD output
  (METR section)
- LINE-MET
- LINE NON-ISOLATED input
  (METR-ZCNI sections)
- L NON-ISOLATED
  INPUT
- CT
- Two shunts cannot be used simultaneously for Primary and secondary for an
  obvious short circuit
  GND_ESD (Pin 95 COMET) shall be routed below the signal lines up to the IC
- Near Comet and
  over M_GND plane
- Near Comet and
  over M_GND plane
- Metrology voltage scaling and current sense
  Use the LCD Module:
          For Metrology Leds,
          Tamper buttons,
          Display buttons,
          LCD,
         3 Phases Metrology connector
sheet 5
- Line Breaker Driver
- RB
- RA
- VR
- GND
- LINE BREAKER
sheet 6
- 3V3_AUX
- SUPPLY FROM BLACK BOX
- PSU
  Connector
- 3V3
- VCC
- 5V
- 3V3
- If possible, add GND plane
  on bottom layer
- Place the x3 inductors near STCOMET
- 3V3 Jack
- 3V3
- GND
- VCC
- VCC
- 5V
- 1V2
- 15V - 200mA
- 5V
- External 1V2 supply possibility
- Connector: correct orientation
  to be respected by EMS
- External PSU selection:
  (Default Setting)
  J9 CLOSED 3-2
  J10 CLOSED 3-2
  J15 CLOSED
  J16 OPEN (page 07)
- External Black Box selection
  J9 CLOSED 2-1
  J10 CLOSED 2-1
  J15 OPEN
  J16 CLOSED (page 07)
- Black-box Internal voltage regulation
- Power supply selection (PSU/Black-box)
- L/N ISOLATED
  INPUTS
- RTC Battery
- LINE ISOLATED input
  (PLC-PSU-ZCI sections)
- L-PLC
- TO PLC and ZCI sections
- N-PLC
- NEUTRAL ISOLATED input
  (PLC-PSU-ZCI sections)
- N
- L
- L/N entrance for ext PSU
- ISOLATED
- Pin 2 must be removed by EMS
- Ground connections
- MGND
- DGND
- AGND
- DGND
- MGND
- AGND
  PGND
- DGND
sheet 7
- The 5V regulator requires
  12uF min for stability
- Metrology Supply
- Analog Supply
- The following DVDD pins should
  be interconnected in the silicon
  and shorted with three powerbars
  in the following groups:
  4, 24
  99, 130
  135,154, 175
  The pins 63 and 83 are isolated
  and MUST be supplied
- (*)
- (*) place C118 near COMET pin 130
  for surges immuity
- Digital Supply
- COMET power supply section
